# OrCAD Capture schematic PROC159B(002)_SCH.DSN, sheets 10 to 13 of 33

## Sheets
10 32. RESET SWITCHES: size C; title: RESET SWITCHES
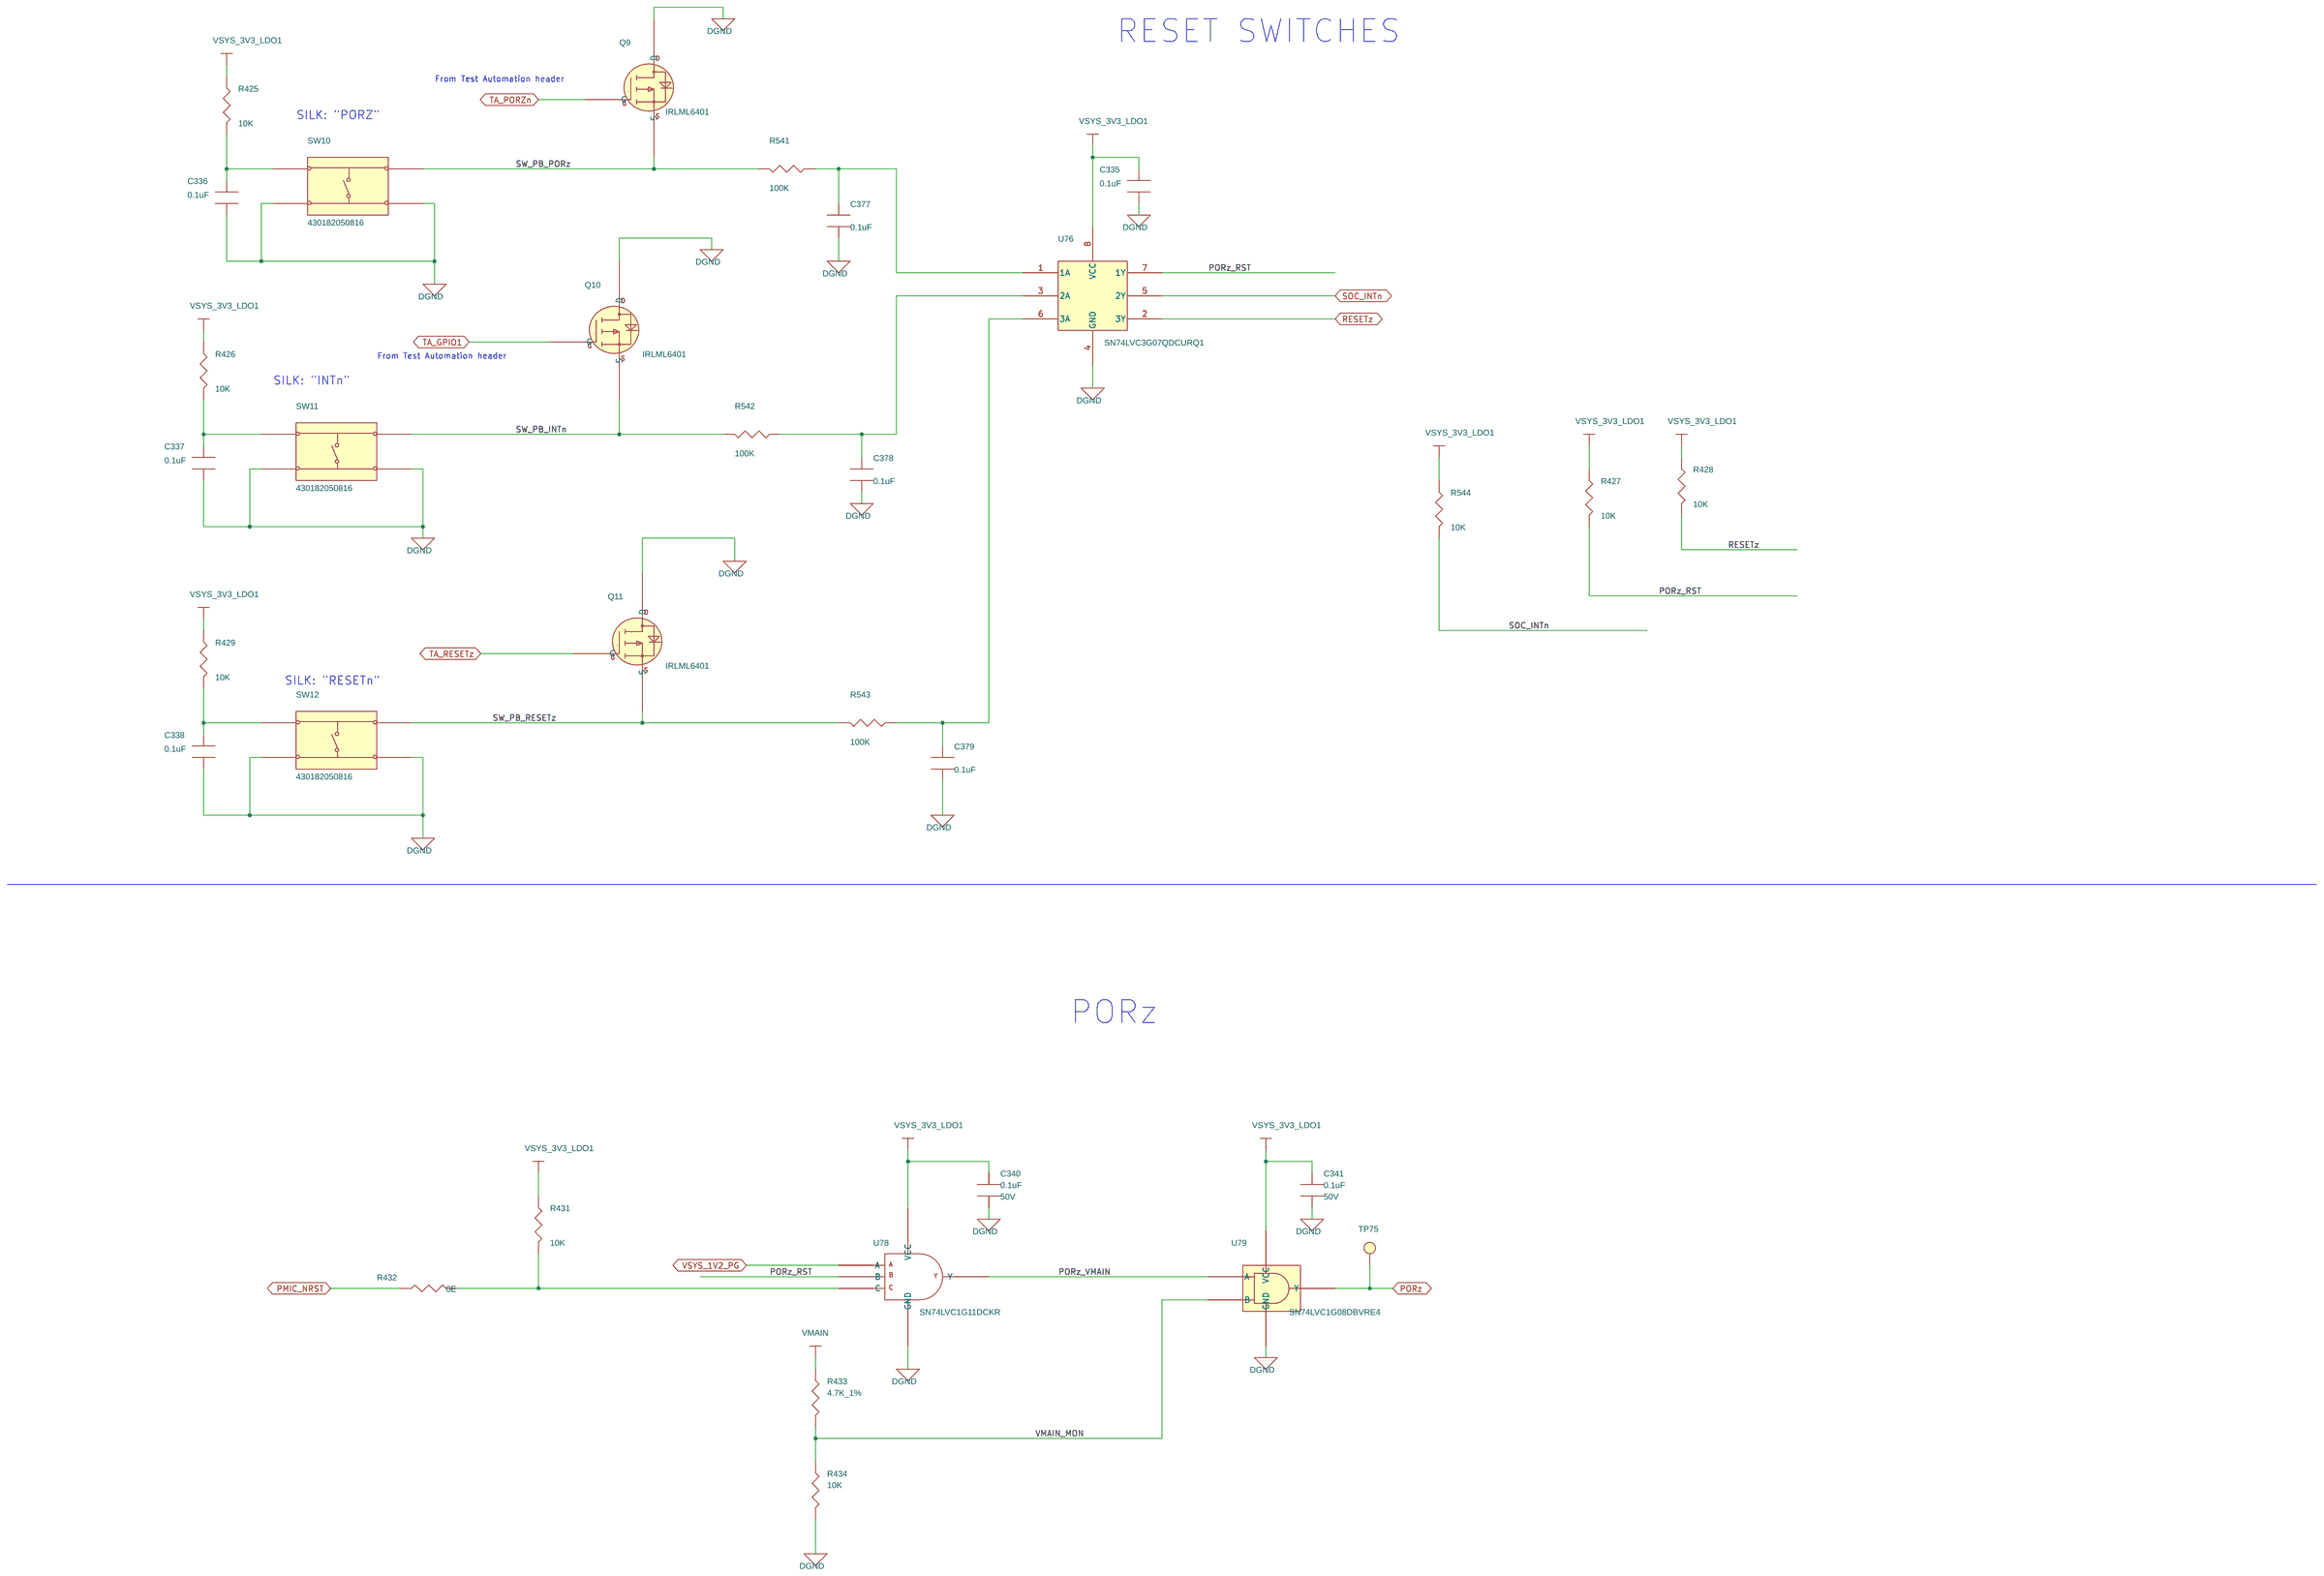
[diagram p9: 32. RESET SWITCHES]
11 25. BOOTMODE BUFFER AND SWITCH: size C; title: BOOTMODE BUFFER AND SWITCH
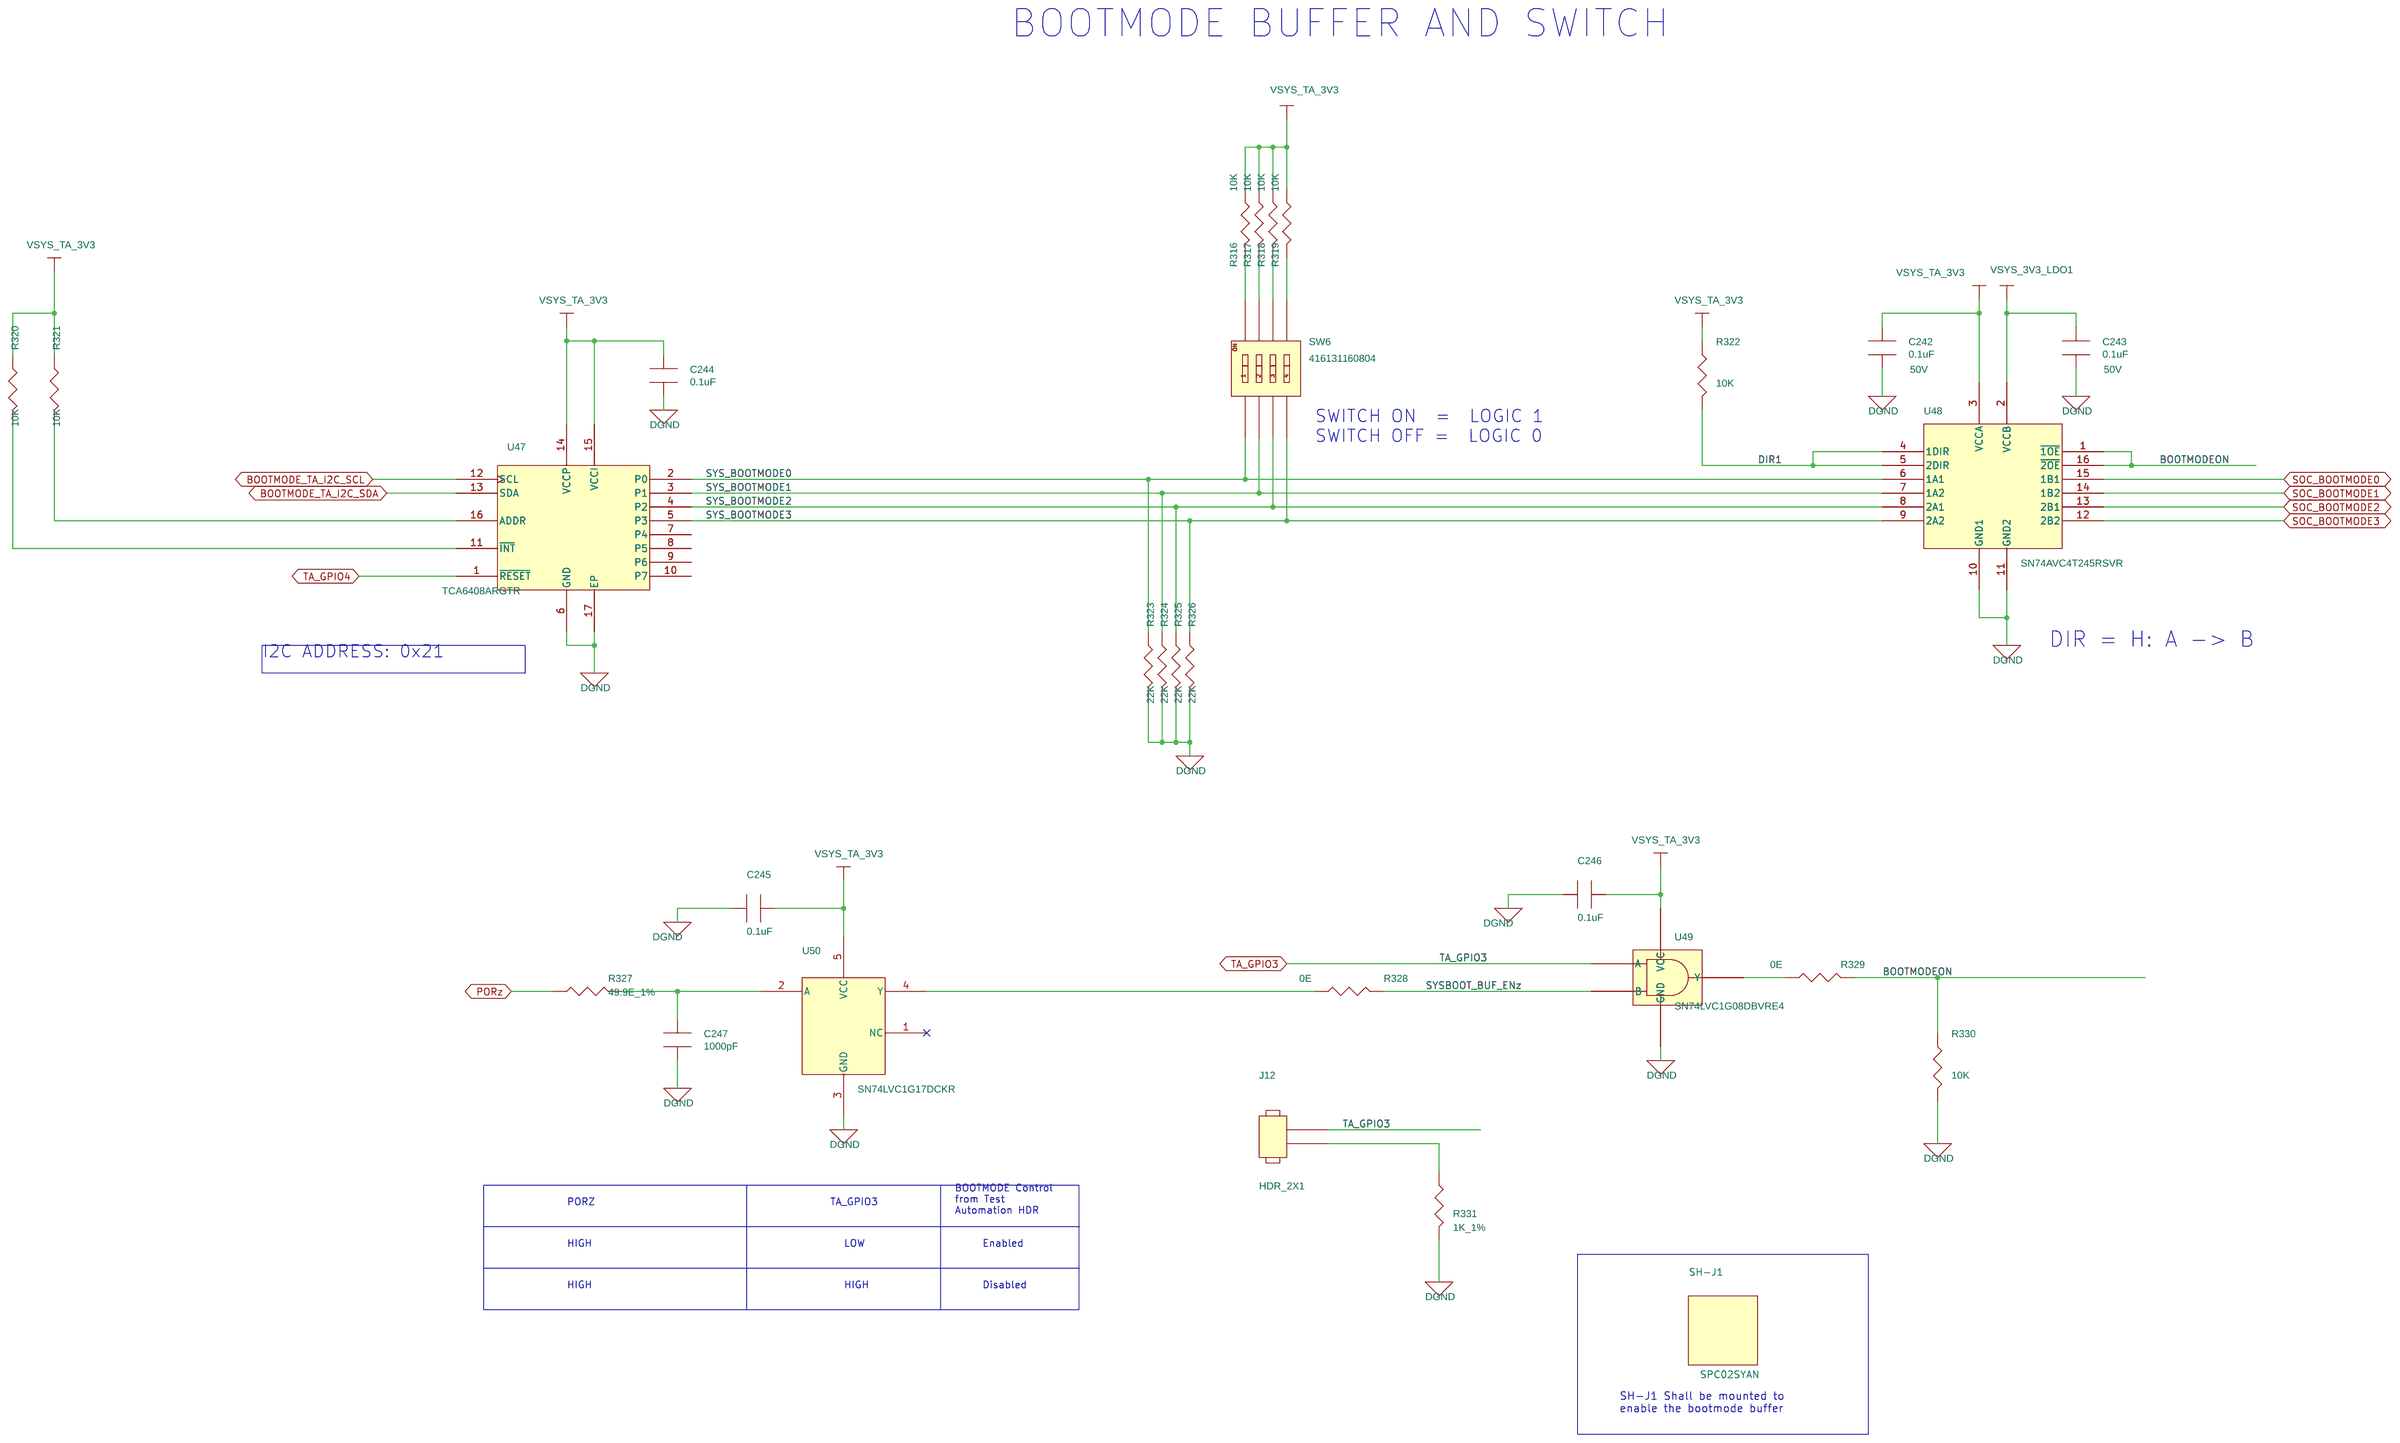
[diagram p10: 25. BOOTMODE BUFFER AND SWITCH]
12 28. LED DRIVER AND IO EXPANDER: size C; title: LED DRIVER AND IO EXPANDER
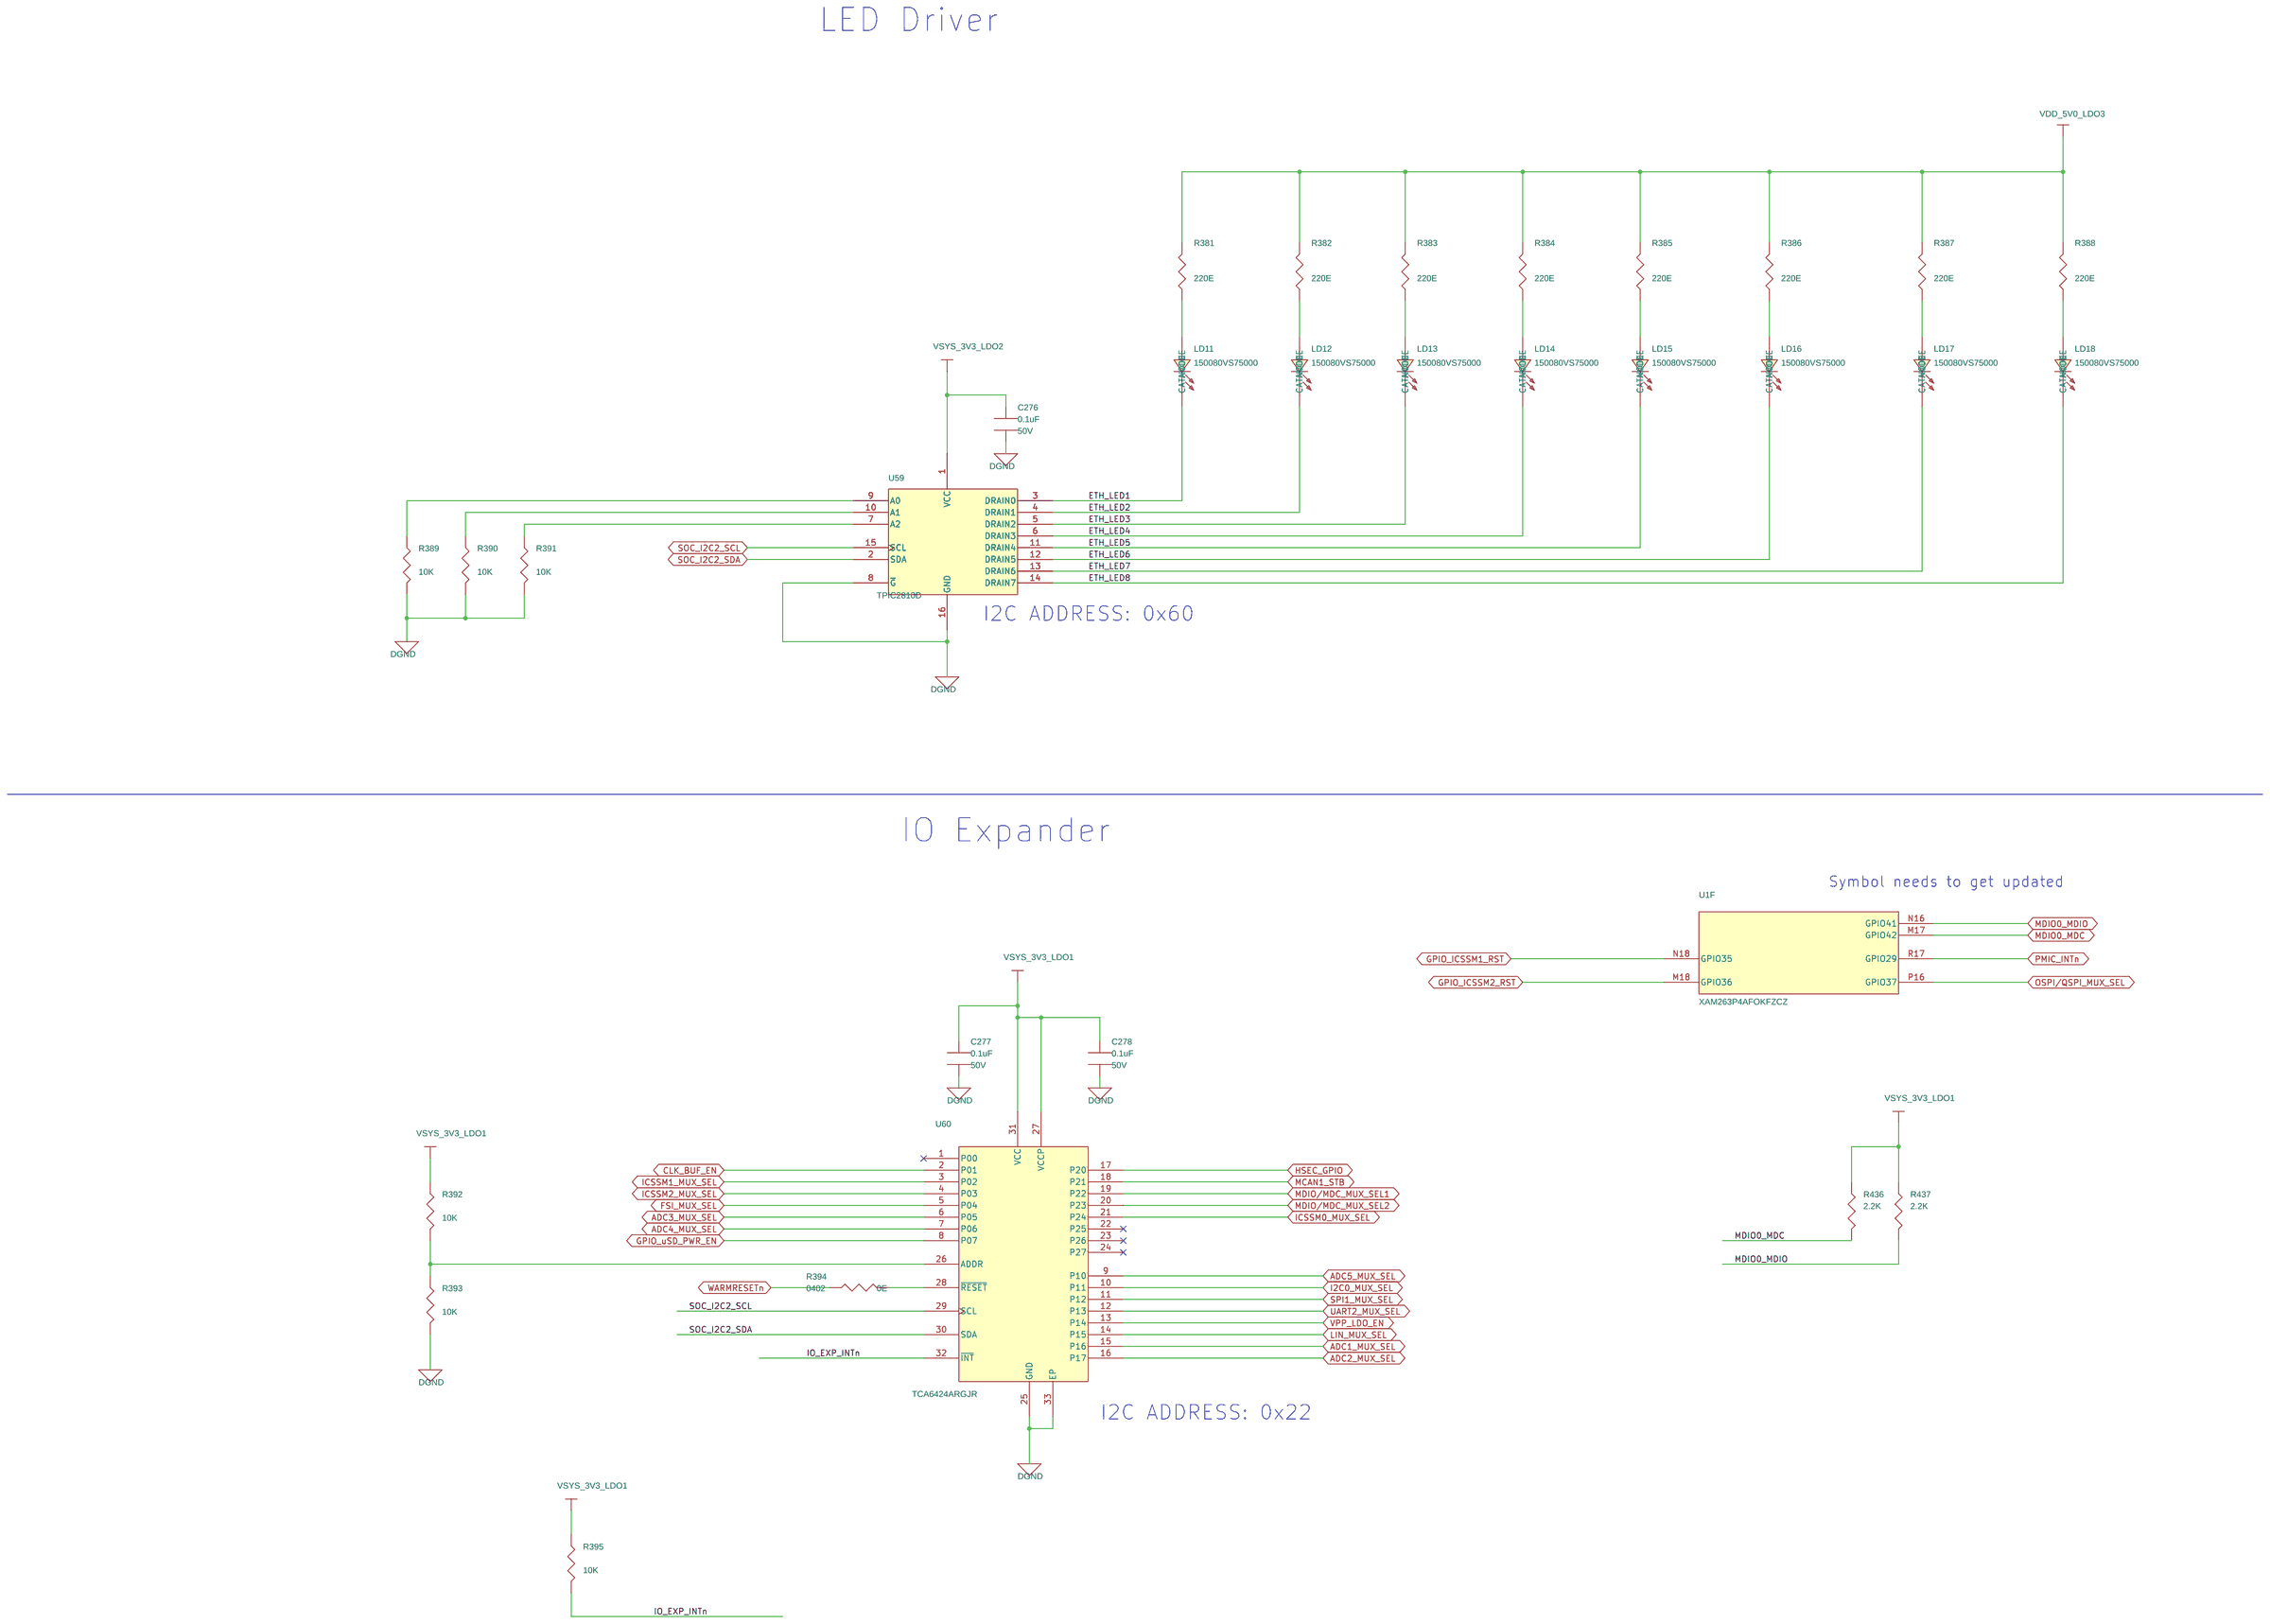
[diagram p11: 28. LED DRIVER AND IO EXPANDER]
13 18. MCAN AND FSI MUX: size C; title: MCAN AND FSI MUX
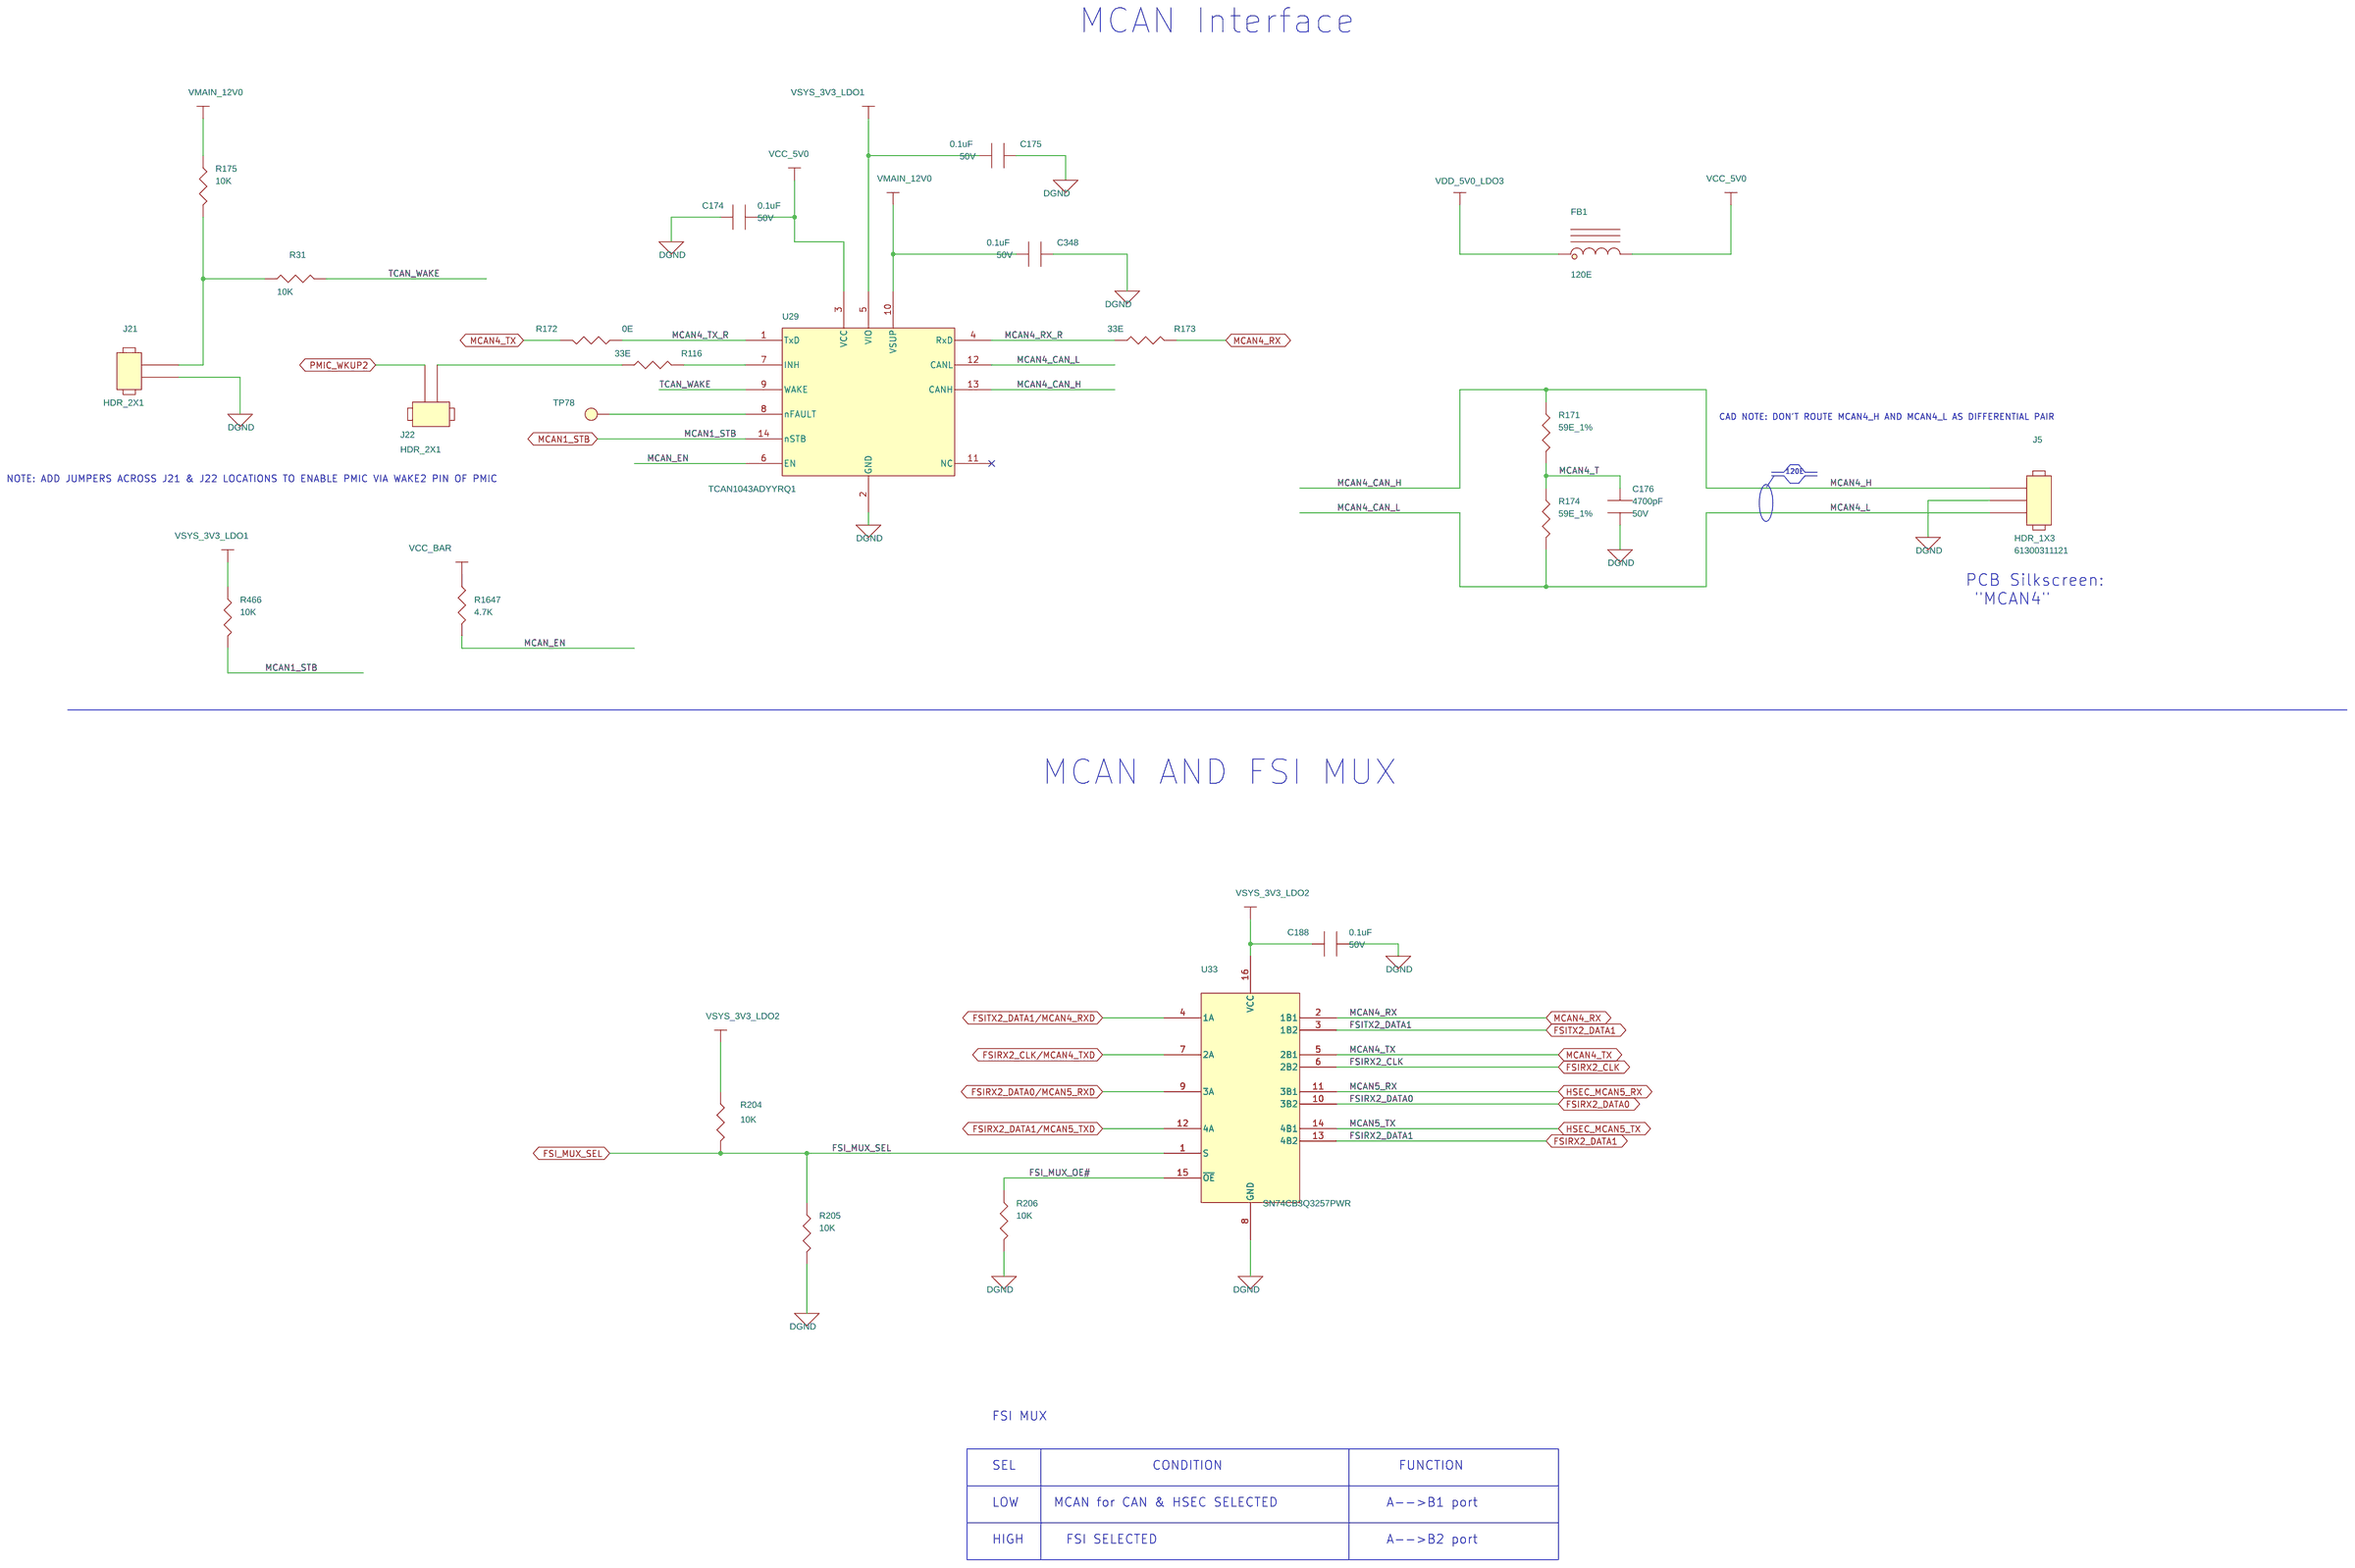
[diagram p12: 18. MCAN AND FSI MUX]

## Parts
sheet 18. MCAN AND FSI MUX
C174  0.1uF  [CAP0402_0-75]
C175  0.1uF  [CAP0402_0-75]
C176  4700pF  [CAP0402_0-75]
C188  0.1uF  [CAP0402_0-75]
C348  0.1uF  [CAP0402_0-75]
FB1  120E  [EMIFIL_BLM18S_0603_0-7]
J5  HDR_1X3  [HDR_1X3_100_S_T]
J21  HDR_2X1  [HDR_2X1_100_S_T_10-8]
J22  HDR_2X1  [HDR_2X1_100_S_T_10-8]
R31  10K  [RES0402_0-5]
R116  33E  [RES0402_0-5]
R171  59E_1%  [RES0402_0-5]
R172  0E  [RES0402_0-5]
R173  33E  [RES0402_0-5]
R174  59E_1%  [RES0402_0-5]
R175  10K  [RES0402_0-5]
R204  10K  [RES0402_0-5]
R205  10K  [RES0402_0-5]
R206  10K  [RES0402_0-5]
R466  10K  [RES0402_0-5]
R1647  4.7K  [RES0402_0-5]
TP78  TP20_SMD  [TP20_SMD]
U29  TCAN1043ADYYRQ1  [SOT23-14_1-1]
U33  SN74CB3Q3257PWR  [TSSOP16_25-59_205X180]
sheet 19. SOC-ICSS DP8386(Indust)
U1  XAM263P4AFOKFZCZ  [BGA324_31-49_590X590_1-4]  (sections A,B,C,D,E,F,G,H,I,J,K,L,M)
sheet 25. BOOTMODE BUFFER AND SWITCH
C242  0.1uF  [CAP0402_0-75]
C243  0.1uF  [CAP0402_0-75]
C244  0.1uF  [CAP0402_0-75]
C245  0.1uF  [CAP0402_0-75]
C246  0.1uF  [CAP0402_0-75]
C247  1000pF  [CAP0402_0-75]
J12  HDR_2X1  [HDR_2X1_100_S_T]
R316  10K  [RES0402_0-5]
R317  10K  [RES0402_0-5]
R318  10K  [RES0402_0-5]
R319  10K  [RES0402_0-5]
R320  10K  [RES0402_0-5]
R321  10K  [RES0402_0-5]
R322  10K  [RES0402_0-5]
R323  22K  [RES0402_0-5]
R324  22K  [RES0402_0-5]
R325  22K  [RES0402_0-5]
R326  22K  [RES0402_0-5]
R327  49.9E_1%  [RES0402_0-5]
R328  0E  [RES0402_0-5]
R329  0E  [RES0402_0-5]
R330  10K  [RES0402_0-5]
R331  1K_1%  [RES0402_0-5]
SH-J1  SPC02SYAN  [NA]
SW6  416131160804  [SW8_416131160804_260X230_SMD_2-7]
U47  TCA6408ARGTR  [QFN16_19-68_120X120_1_EP1-6]
U48  SN74AVC4T245RSVR  [UQFN16_TMUX1574_70X100_0-6]
U49  SN74LVC1G08DBVRE4  [SOT23-5]
U50  SN74LVC1G17DCKR  [SC70-5]
sheet 28. LED DRIVER AND IO EXPANDER
C276  0.1uF  [CAP0402_0-75]
C277  0.1uF  [CAP0402_0-75]
C278  0.1uF  [CAP0402_0-75]
LD11  150080VS75000  [LED_150080VS75000_80X50_SMD_0-8]
LD12  150080VS75000  [LED_150080VS75000_80X50_SMD_0-8]
LD13  150080VS75000  [LED_150080VS75000_80X50_SMD_0-8]
LD14  150080VS75000  [LED_150080VS75000_80X50_SMD_0-8]
LD15  150080VS75000  [LED_150080VS75000_80X50_SMD_0-8]
LD16  150080VS75000  [LED_150080VS75000_80X50_SMD_0-8]
LD17  150080VS75000  [LED_150080VS75000_80X50_SMD_0-8]
LD18  150080VS75000  [LED_150080VS75000_80X50_SMD_0-8]
R381  220E  [RES0402_0-5]
R382  220E  [RES0402_0-5]
R383  220E  [RES0402_0-5]
R384  220E  [RES0402_0-5]
R385  220E  [RES0402_0-5]
R386  220E  [RES0402_0-5]
R387  220E  [RES0402_0-5]
R388  220E  [RES0402_0-5]
R389  10K  [RES0402_0-5]
R390  10K  [RES0402_0-5]
R391  10K  [RES0402_0-5]
R392  10K  [RES0402_0-5]
R393  10K  [RES0402_0-5]
R394  0E  [RES0402_0-5]
R395  10K  [RES0402_0-5]
R436  2.2K  [RES0402_0-5]
R437  2.2K  [RES0402_0-5]
U59  TPIC2810D  [SOIC16_1-8]
U60  TCA6424ARGJR  [QFN32_19-68_200X200]
sheet 32. RESET SWITCHES
C335  0.1uF  [CAP0402_0-75]
C336  0.1uF  [CAP0402_0-75]
C337  0.1uF  [CAP0402_0-75]
C338  0.1uF  [CAP0402_0-75]
C340  0.1uF  [CAP0402_0-75]
C341  0.1uF  [CAP0402_0-75]
C377  0.1uF  [CAP0402_0-75]
C378  0.1uF  [CAP0402_0-75]
C379  0.1uF  [CAP0402_0-75]
Q9  IRLML6401  [TO_SOT23-123]
Q10  IRLML6401  [TO_SOT23-123]
Q11  IRLML6401  [TO_SOT23-123]
R425  10K  [RES0402_0-5]
R426  10K  [RES0402_0-5]
R427  10K  [RES0402_0-5]
R428  10K  [RES0402_0-5]
R429  10K  [RES0402_0-5]
R431  10K  [RES0402_0-5]
R432  0E  [RES0402_0-5]
R433  4.7K_1%  [RES0402_0-5]
R434  10K  [RES0402_0-5]
R541  100K  [RES0402_0-5]
R542  100K  [RES0402_0-5]
R543  100K  [RES0402_0-5]
R544  10K  [RES0402_0-5]
SW10  430182050816  [SW4_430182050816_240X240_SMD_5-2]
SW11  430182050816  [SW4_430182050816_240X240_SMD_5-2]
SW12  430182050816  [SW4_430182050816_240X240_SMD_5-2]
TP75  TP40_SMD  [TP40_SMD]
U76  SN74LVC3G07QDCURQ1  [VSSOP8_19-68_85X95]
U78  SN74LVC1G11DCKR  [SC70-6]
U79  SN74LVC1G08DBVRE4  [SOT23-5]

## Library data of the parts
C174 C175 C348 = CAP: CAP CERAMIC 0.1uF 50V 10% X7R 0402; Automotive Alternate_mfr_name: TDK; Automotive Alternate_mfr_part_number: CGA2B1X7R1C104K050BC; Chkd/date: MANIRAJA/261020; Crtd /date: ALVY/211020; Custom_Duty: 15%; Customs_HS_Code: 85322990; Direct Alternate_mfr_name: MURATA; Direct Alternate_mfr_part_number: GCM155R71C104JA55D; Distributor_name: DIGIKEY; Distributor_part_number: 490-10700-1-ND; Footprint Path: Y:\MIS_DATABASE\Library\ALTIUM_TOOL\PCB_FOOTPRINTS\Altium_Footprint_Lib.PcbLib; Height: 0.55MM; Library Path: Y:\MIS_DATABASE\Library\ALTIUM_TOOL\SCHEMATICS_PARTS\MS_DISCRETE_Library.schlib; Mfr_name: MURATA; Mfr_part_number: GRM155R71H104KE14D; Mistral Part No: 120011100014-R; Package: 0402; Part_type: CAPACITORS\CERAMIC; Project: J7_CP; RoHS: RoHS; Temperature: -55°C+125°C; Tolerance: 10%; Voltage: 50V; Wattage: NA; Weight: 3.1mg; Datasheet: Y:\MIS_DATABASE\DATASHEETS\CAPACITORS\GRM155R71H104KE14.PDF
C176 = CAP: CAP CERAMIC 4700pF 50V 10% X7R 0402; Automotive Alternate_mfr_name: TDK; Automotive Alternate_mfr_part_number: CGA2B2X7R1H472K050BA; Chkd/date: MANIRAJA/040419; Crtd /date: MANIRAJA/040419; Custom_Duty: 15%; Customs_HS_Code: 85322990; Direct Alternate_mfr_name: SAMSUNG; Direct Alternate_mfr_part_number: CL05B472KB5NNNC; Distributor_name: DIGIKEY; Distributor_part_number: 490-1308-1-ND; Footprint Path: Y:\MIS_DATABASE\Library\ALTIUM_TOOL\PCB_FOOTPRINTS\Altium_Footprint_Lib.PcbLib; Height: 0.55MM; Library Path: Y:\MIS_DATABASE\Library\ALTIUM_TOOL\SCHEMATICS_PARTS\MS_DISCRETE_Library.schlib; Mfr_name: MURATA; Mfr_part_number: GRM155R71H472KA01D; Mistral Part No: 120009030440-R; Package: 0402; Part_type: CAPACITORS\CERAMIC; Project: RED EYE; RoHS: RoHS; Temperature: -55°C+125°C; Tolerance: 10%; Voltage: 50V; Wattage: NA; Weight: 0.65mg; Datasheet: Y:\MIS_DATABASE\DATASHEETS\CAPACITORS\GRM155R71H472KA01.PDF
C188 C277 C278 C335-C338 C340 = CAP: CAP CERAMIC 0.1uF 50V 10% X7R 0402; Automotive Alternate_mfr_name: TDK; Automotive Alternate_mfr_part_number: CGA2B3X7R1H104K050BB; Chkd/date: MANIRAJA/261020; Crtd /date: ALVY/211020; Custom_Duty: 15%; Customs_HS_Code: 85322990; Direct Alternate_mfr_name: TDK; Direct Alternate_mfr_part_number: C1005X7R1H104K050BE; Distributor_name: DIGIKEY; Distributor_part_number: 490-10700-1-ND; Footprint Path: Y:\MIS_DATABASE\Library\ALTIUM_TOOL\PCB_FOOTPRINTS\Altium_Footprint_Lib.PcbLib; Height: 0.55MM; Library Path: Y:\MIS_DATABASE\Library\ALTIUM_TOOL\SCHEMATICS_PARTS\MS_DISCRETE_Library.schlib; Mfr_name: MURATA; Mfr_part_number: GRM155R71H104KE14D; Mistral Part No: 120011100014-R; Package: 0402; Part_type: CAPACITORS\CERAMIC; Project: J7_CP; RoHS: RoHS; Temperature: -55°C+125°C; Tolerance: 10%; Voltage: 50V; Wattage: NA; Weight: 3.1mg; Datasheet: Y:\MIS_DATABASE\DATASHEETS\CAPACITORS\GRM155R71H104KE14.PDF
FB1 = INDUCTOR_FERRITE: PASSIVE FILTER CHIP 120E 3A 0603; Chkd/date: MANIRAJA/241017; Crtd /date: BAVISH/080811; Custom_Duty: 24%; Customs_HS_Code: 85437099; Distributor_name: DIGIKEY; Distributor_part_number: 490-3996-1-ND; Height: 0.65MM; Mfr_name: MURATA; Mfr_part_number: BLM18SG121TN1D; Mistral Part No: 130011080020-R; Package: 0603; Part_type: FILTER; Project: ACRO_DM3730; RoHS: RoHS; Temperature: -55°C+125°C; Tolerance: NA; Voltage: NA; Wattage: NA; Weight: NA; Datasheet: Y:\MIS_DATABASE\DATASHEETS\DISCRETES\INDUCTORS\BLM18S.PDF
J5 = HEADER_3X1: CON HDR 1X3 2.54MM PITCH ST TH; Chkd/date: VASANTHA/211015; Crtd /date: VASANTHA/211015; Custom_Duty: 24%; Customs_HS_Code: 85369090; Distributor_name: DIGIKEY; Distributor_part_number: 732-5316-ND; Height: 8.54MM; Mfr_name: WURTH ELECTRONICS INC; Mfr_part_number: 61300311121; Mistral Part No: 150015100037-R; Package: THRU-HOLE; Part_type: CONNECTOR\HEADERS; Project: CYPHY_ROADKILL; RoHS: RoHS; Temperature: NA; Tolerance: NA; Voltage: NA; Wattage: NA; Weight: NA; Datasheet: Y:\MIS_DATABASE\DATASHEETS\CONNECTORS\6130XXX.PDF
J21 J22 = HEADER_2X1: CON HDR 2X1 2.54MM PITCH ST TH; Chkd/date: VASANTHA/060117; Crtd /date: MAZHAR/280405; Custom_Duty: 24%; Customs_HS_Code: 85369090; Distributor_name: DIGIKEY; Distributor_part_number: WM4000-ND; Footprint Path: Y:\MIS_DATABASE\Library\ALTIUM_TOOL\PCB_FOOTPRINTS\Altium_Footprint_Lib.PcbLib; Height: 10.79MM; Library Path: Y:\MIS_DATABASE\Library\ALTIUM_TOOL\SCHEMATICS_PARTS\MS_CONNECTOR_Library.schlib; Mfr_name: MOLEX; Mfr_part_number: 22-03-2021; Mistral Part No: 150009030246-R; Package: THRU-HOLE; Part_type: CONNECTOR\HEADERS; Project: FPGA EXTENDER CARD; RoHS: RoHS; Temperature: -0°C+75°C; Tolerance: NA; Voltage: NA; Wattage: NA; Weight: 139gm; Datasheet: Y:\MIS_DATABASE\DATASHEETS\CONNECTORS\HEADER_X4030.PDF
R31 R175 R205 R206 R466 = RESISTOR: RES 10K 1/16W 5% 0402; Assembly_Instruction: DNI; Chkd/date: VASANTHA/061216; Crtd /date: MAZHAR/230805; Custom_Duty: 15%; Customs_HS_Code: 85332119; Distributor_name: DIGIKEY; Distributor_part_number: 311-10KJRCT-ND; Footprint Path: Y:\MIS_DATABASE\Library\ALTIUM_TOOL\PCB_FOOTPRINTS\Altium_Footprint_Lib.PcbLib; Height: 0.40MM; Library Path: Y:\MIS_DATABASE\Library\ALTIUM_TOOL\SCHEMATICS_PARTS\MS_DISCRETE_Library.schlib; Mfr_name: YAGEO AMERICA; Mfr_part_number: RC0402JR-0710KL; Mistral Part No: 110011060021-R; Package: 0402; Part_type: RESISTORS\FIXED; Project: HSE; RoHS: RoHS; Temperature: -55°C+155°C; Tolerance: 5%; Voltage: NA; Wattage: 1/16W; Weight: 0.65mg; Datasheet: Y:\MIS_DATABASE\DATASHEETS\RESISTORS\RCXXXXL-SER_MAR18.PDF
R116 R173 = RESISTOR: RES 33E 1/10W 5% 0402; Chkd/date: VASANTHA/201216; Crtd /date: GEETHA/190406; Custom_Duty: 15%; Customs_HS_Code: 85332119; Distributor_name: DIGIKEY; Distributor_part_number: P33JCT-ND; Footprint Path: Y:\MIS_DATABASE\Library\ALTIUM_TOOL\PCB_FOOTPRINTS\Altium_Footprint_Lib.PcbLib; Height: 0.40MM; Library Path: Y:\MIS_DATABASE\Library\ALTIUM_TOOL\SCHEMATICS_PARTS\MS_DISCRETE_Library.schlib; Mfr_name: PANASONIC-ECG; Mfr_part_number: ERJ-2GEJ330X; Mistral Part No: 110009030699-R; Package: 0402; Part_type: RESISTORS\FIXED; Project: RED EYE; RoHS: RoHS; Temperature: -55°C+155°C; Tolerance: 5%; Voltage: NA; Wattage: 1/10W; Weight: 0.8mg; Datasheet: Y:\MIS_DATABASE\DATASHEETS\RESISTORS\PAN-ERJSER_NOV17.PDF
R171 R174 = RESISTOR: RES 59E 1/10W 1% 0402; Chkd/date: MAZHAR/151208; Crtd /date: USMAN/031208; Custom_Duty: 15%; Customs_HS_Code: 85332119; Distributor_name: DIGIKEY; Distributor_part_number: P59.0LCT-ND; Footprint Path: Y:\MIS_DATABASE\Library\ALTIUM_TOOL\PCB_FOOTPRINTS\Altium_Footprint_Lib.PcbLib; Height: 0.40MM; Library Path: Y:\MIS_DATABASE\Library\ALTIUM_TOOL\SCHEMATICS_PARTS\MS_DISCRETE_Library.schlib; Mfr_name: PANASONIC-ECG; Mfr_part_number: ERJ-2RKF59R0X; Mistral Part No: 110009031010-R; Package: 0402; Part_type: RESISTORS\FIXED; Project: KHAN_HSST; RoHS: RoHS; Temperature: -55°C+155°C; Tolerance: 1%; Voltage: NA; Wattage: 1/10W; Weight: 0.8mg; Datasheet: Y:\MIS_DATABASE\DATASHEETS\RESISTORS\PAN-ERJSER_NOV17.PDF
R172 R328 R329 R394 R432 = RESISTOR: RES 0E 1/10W JUMPER 0402; Chkd/date: VASANTHA/061216; Crtd /date: NAVEED/201014; Custom_Duty: 15%; Customs_HS_Code: 85332119; Distributor_name: DIGIKEY; Distributor_part_number: P0.0JCT-ND; Footprint Path: Y:\MIS_DATABASE\Library\ALTIUM_TOOL\PCB_FOOTPRINTS\Altium_Footprint_Lib.PcbLib; Height: 0.40MM; IBISSP_MODLES: VALUE REPEATING 2 TIME; Library Path: Y:\MIS_DATABASE\Library\ALTIUM_TOOL\SCHEMATICS_PARTS\MS_DISCRETE_Library.schlib; Mfr_name: PANASONIC-ECG; Mfr_part_number: ERJ-2GE0R00X; Mistral Part No: 110018030052-R; Package: 0402; Part_type: RESISTORS\FIXED; Project: AEGIS POM; RoHS: RoHS; Temperature: -55°C+155°C; Tolerance: NA; Voltage: NA; Wattage: 1/10W; Weight: 0.8mg; Datasheet: Y:\MIS_DATABASE\DATASHEETS\RESISTORS\PAN-ERJSER_NOV17.PDF
R204 R316-R322 R330 R389-R393 R395 R425-R429 R431 R434 R544 = RESISTOR: RES 10K 1/16W 5% 0402; Chkd/date: VASANTHA/061216; Crtd /date: MAZHAR/230805; Custom_Duty: 15%; Customs_HS_Code: 85332119; Distributor_name: DIGIKEY; Distributor_part_number: 311-10KJRCT-ND; Footprint Path: Y:\MIS_DATABASE\Library\ALTIUM_TOOL\PCB_FOOTPRINTS\Altium_Footprint_Lib.PcbLib; Height: 0.40MM; Library Path: Y:\MIS_DATABASE\Library\ALTIUM_TOOL\SCHEMATICS_PARTS\MS_DISCRETE_Library.schlib; Mfr_name: YAGEO AMERICA; Mfr_part_number: RC0402JR-0710KL; Mistral Part No: 110011060021-R; Package: 0402; Part_type: RESISTORS\FIXED; Project: HSE; RoHS: RoHS; Temperature: -55°C+155°C; Tolerance: 5%; Voltage: NA; Wattage: 1/16W; Weight: 0.65mg; Datasheet: Y:\MIS_DATABASE\DATASHEETS\RESISTORS\RCXXXXL-SER_MAR18.PDF
R1647 = RESISTOR: RES 4.7K 1/16W 5% 0402; Chkd/date: VASANTHA/281216; Crtd /date: BAVISH/010611; Custom_Duty: 15%; Customs_HS_Code: 85332119; Distributor_name: DIGIKEY; Distributor_part_number: 541-4.7KJCT-ND; Footprint Path: Y:\MIS_DATABASE\Library\ALTIUM_TOOL\PCB_FOOTPRINTS\Altium_Footprint_Lib.PcbLib; Height: 0.40MM; Library Path: Y:\MIS_DATABASE\Library\ALTIUM_TOOL\SCHEMATICS_PARTS\MS_DISCRETE_Library.schlib; Mfr_name: VISHAY; Mfr_part_number: CRCW04024K70JNED; Mistral Part No: 110011060001-R; Package: 0402; Part_type: RESISTORS\FIXED; Project: AM4515_EVM_LCD; RoHS: RoHS; Temperature: -55°C+155°C; Tolerance: 5%; Voltage: NA; Wattage: 1/16W; Weight: 0.65mg; Datasheet: Y:\MIS_DATABASE\DATASHEETS\RESISTORS\CRCW0603.PDF
TP78 = TESTPOINT: TESTPOINT CIR 20 SMD; Chkd/date: SHREESHAIL/171006; Crtd /date: MAZHAR/171006; Custom_Duty: NA; Customs_HS_Code: NA; Distributor_name: NA; Distributor_part_number: NA; Footprint Path: Y:\MIS_DATABASE\Library\ALTIUM_TOOL\PCB_FOOTPRINTS\Altium_Footprint_Lib.PcbLib; Height: NA; Library Path: Y:\MIS_DATABASE\Library\ALTIUM_TOOL\SCHEMATICS_PARTS\MS_DISCRETE_Library.schlib; MECHANICAL 3D STEP FILE: NA; Mfr_name: LOCAL; Mistral Part No: NA; Package: SMD; Project: BT MODULE_CSRBC04; RoHS: NA; Temperature: NA; Tolerance: NA; Voltage: NA; Wattage: NA; Weight: NA; Datasheet: NA
U29 = TCAN1043DQ1_SOIC14: IC AUTOMOTIVE LOW-POWER FAULT PROTECTED CAN FD TRANSCEIVER WITH SLEEP MODE TSOT23-14; Chkd/date: ALVY/140422; Crtd /date: ALVY/140422; Custom_Duty: 15%; Customs_HS_Code: 85423100; Distributor_name: NA; Distributor_part_number: NA; Footprint Path: Y:\MIS_DATABASE\Library\ALTIUM_TOOL\PCB_FOOTPRINTS\Altium_Footprint_Lib.PcbLib; Height: 1.10MM; Library Path: Y:\MIS_DATABASE\Library\ALTIUM_TOOL\SCHEMATICS_PARTS\MS_TELECOM_Library.schlib; Mfr_name: TEXAS INSTRUMENTS; Mistral Part No: 143022040001-R; Package: TSOT23-14; Part_type: ICS\TELECOM\TRANSCEIVER; Project: TI_AM62A SVB_BRD; RoHS: NA; Temperature: -40°C+150°C; Tolerance: NA; Voltage: NA; Wattage: NA; Weight: NA; Datasheet: Y:\MIS_DATABASE\DATASHEETS\ICS\TELECOM\TCAN1043-Q1.PDF
U33 = SN74CB3Q3257PWR_TSSOP16: IC 4BIT 1-OF-2 FET MULTIPLEXER/DEMULTIPLEXER TSSOP16; Chkd/date: SUHAS/251010; Crtd /date: USMAN/060109; Custom_Duty: 15%; Customs_HS_Code: 85423100; Distributor_name: DIGIKEY; Distributor_part_number: 296-19138-1-ND; Height: 1.20MM; Mfr_name: TEXAS INSTRUMENTS; Mistral Part No: 141009030117-R; Package: TSSOP16; Part_type: ICS\DIGITAL\COMBINATIONAL; Project: OMAP_EVM; RoHS: Sb/ Br FREE; Temperature: -40°C+85°C; Datasheet: Y:\MIS_DATABASE\DATASHEETS\ICS\DIGITAL\COMBINATIONAL\SN74CB3Q3257.PDF
U1 = XAM263P4ASOKFZCZ_BGA324: IC SIP AM263P SoC BGA324; Chkd/date: PRADEEP/030124; Crtd /date: PRADEEP/030124; Custom_Duty: 15%; Customs_HS_Code: 85423100; Distributor_name: NA; Distributor_part_number: NA; Footprint Path: Y:\MIS_DATABASE\Library\ALTIUM_TOOL\PCB_FOOTPRINTS\Altium_Footprint_Lib.PcbLib; Height: 1.40MM; MECHANICAL 3D STEP FILE: NA; Mfr_name: TEXAS INSTRUMENTS; Mistral Part No: 141324010001; Package: BGA324; Part_type: ICS\DIGITAL\FPGA; Project: AM263P_CC; RoHS: RoHS; Temperature: NA; Tolerance: NA; Voltage: NA; Wattage: NA; Weight: NA; Datasheet: Y:\MIS_DATABASE\DATASHEETS\ICS\INTERFACE\ZCZ0324A.PDF
C242-C246 C276 C341 = CAP: CAP CERAMIC 0.1uF 50V 10% X7R 0402; Chkd/date: MANIRAJA/261020; Crtd /date: ALVY/211020; Custom_Duty: 15%; Customs_HS_Code: 85322990; Distributor_name: DIGIKEY; Distributor_part_number: 490-10700-1-ND; Footprint Path: Y:\MIS_DATABASE\Library\ALTIUM_TOOL\PCB_FOOTPRINTS\Altium_Footprint_Lib.PcbLib; Height: 0.55MM; Library Path: Y:\MIS_DATABASE\Library\ALTIUM_TOOL\SCHEMATICS_PARTS\MS_DISCRETE_Library.schlib; Mfr_name: MURATA; Mfr_part_number: GRM155R71H104KE14D; Mistral Part No: 120011100014-R; Package: 0402; Part_type: CAPACITORS\CERAMIC; Project: J7_CP; RoHS: RoHS; Temperature: -55°C+125°C; Tolerance: 10%; Voltage: 50V; Wattage: NA; Weight: 3.1mg; Datasheet: Y:\MIS_DATABASE\DATASHEETS\CAPACITORS\GRM155R71H104KE14.PDF
C247 = CAP: CAP CERAMIC 1000pF 50V 5% C0G(NP0) 0402; Chkd/date: VASANTHA/281216; Crtd /date: MAZHAR/290806; Custom_Duty: 15%; Customs_HS_Code: 85322990; Distributor_name: DIGIKEY; Distributor_part_number: 490-3244-1-ND; Footprint Path: Y:\MIS_DATABASE\Library\ALTIUM_TOOL\PCB_FOOTPRINTS\Altium_Footprint_Lib.PcbLib; Height: 0.55MM; Library Path: Y:\MIS_DATABASE\Library\ALTIUM_TOOL\SCHEMATICS_PARTS\MS_DISCRETE_Library.schlib; Mfr_name: MURATA; Mfr_part_number: GRM1555C1H102JA01D; Mistral Part No: 120016110009-R; Package: 0402; Part_type: CAPACITORS\CERAMIC; Project: SVDO_RMB_MMA; RoHS: RoHS; Temperature: -55°C+125°C; Tolerance: 5%; Voltage: 50V; Wattage: NA; Weight: 6mg; Datasheet: Y:\MIS_DATABASE\DATASHEETS\CAPACITORS\MURATA-GXX-SER_NOV17.PDF
J12 = HEADER_2X1: CON HDR 2X1 2.54MM PITCH ST TH; Chkd/date: NAVEED/210714; Crtd /date: USMAN/031012; Custom_Duty: 24%; Customs_HS_Code: 85369090; Distributor_name: DIGIKEY; Distributor_part_number: WM8072-ND; Height: 5.60MM; Mfr_name: MOLEX; Mfr_part_number: 90120-0122; Mistral Part No: 150012100005-R; Package: THRU-HOLE; Part_type: CONNECTOR\HEADERS; Project: NPOL_FEP; RoHS: RoHS; Temperature: -55°C+125°C; Tolerance: NA; Voltage: NA; Wattage: NA; Weight: NA; Datasheet: Y:\MIS_DATABASE\DATASHEETS\CONNECTORS\90120-SERIES.PDF
R323-R326 = RESISTOR: RES 22K 1/16W 5% 0402; Chkd/date: MANIRAJA/310718; Crtd /date: BAVISH/021210; Custom_Duty: 15%; Customs_HS_Code: 85332119; Distributor_name: DIGIKEY; Distributor_part_number: 311-22KJRCT-ND; Footprint Path: Y:\MIS_DATABASE\Library\ALTIUM_TOOL\PCB_FOOTPRINTS\Altium_Footprint_Lib.PcbLib; Height: 0.40MM; Library Path: Y:\MIS_DATABASE\Library\ALTIUM_TOOL\SCHEMATICS_PARTS\MS_DISCRETE_Library.schlib; Mfr_name: YAGEO AMERICA; Mfr_part_number: RC0402JR-0722KL; Mistral Part No: 110010120021-R; Package: 0402; Part_type: RESISTORS\FIXED; Project: TE4; RoHS: RoHS; Temperature: -55°C+155°C; Tolerance: 5%; Voltage: NA; Wattage: 1/16W; Weight: 0.65mg; Datasheet: Y:\MIS_DATABASE\DATASHEETS\RESISTORS\RCXXXXL-SER_MAR18.PDF
R327 = RESISTOR: RES 49.9E 1/10W 1% 0402; Chkd/date: VASANTHA/201216; Crtd /date: MAZHAR/201005; Custom_Duty: 15%; Customs_HS_Code: 85332119; Distributor_name: DIGIKEY; Distributor_part_number: P49.9LCT-ND; Footprint Path: Y:\MIS_DATABASE\Library\ALTIUM_TOOL\PCB_FOOTPRINTS\Altium_Footprint_Lib.PcbLib; Height: 0.40MM; Library Path: Y:\MIS_DATABASE\Library\ALTIUM_TOOL\SCHEMATICS_PARTS\MS_DISCRETE_Library.schlib; Mfr_name: PANASONIC-ECG; Mfr_part_number: ERJ-2RKF49R9X; Mistral Part No: 110009030897-R; Package: 0402; Part_type: RESISTORS\FIXED; Project: RED EYE; RoHS: RoHS; Temperature: -55°C+155°C; Tolerance: 1%; Voltage: NA; Wattage: 1/10W; Weight: 0.8mg; Datasheet: Y:\MIS_DATABASE\DATASHEETS\RESISTORS\PAN-ERJSER_NOV17.PDF
R331 = RESISTOR: RES 1K 1/10W 1% 0402; Chkd/date: VASANTHA/281216; Crtd /date: MAZHAR/150506; Custom_Duty: 15%; Customs_HS_Code: 85332119; Distributor_name: DIGIKEY; Distributor_part_number: P1.00KLCT-ND; Footprint Path: Y:\MIS_DATABASE\Library\ALTIUM_TOOL\PCB_FOOTPRINTS\Altium_Footprint_Lib.PcbLib; Height: 0.40MM; Library Path: Y:\MIS_DATABASE\Library\ALTIUM_TOOL\SCHEMATICS_PARTS\MS_DISCRETE_Library.schlib; Mfr_name: PANASONIC-ECG; Mfr_part_number: ERJ-2RKF1001X; Mistral Part No: 110009030411-R; Package: 0402; Part_type: RESISTORS\FIXED; Project: VOCERA; RoHS: RoHS; Temperature: -55°C+155°C; Tolerance: 1%; Voltage: NA; Wattage: 1/10W; Weight: 0.8mg; Datasheet: Y:\MIS_DATABASE\DATASHEETS\RESISTORS\PAN-ERJSER_NOV17.PDF
SH-J1 = ACCESSORY: ACCESSORIE JUMPER SHORTING GOLD FLASH; Chkd/date: SUHAS\211010; Crtd /date: USMAN/301208; Distributor_name: DIGIKEY; Distributor_part_number: S9001-ND; Footprint Path: Y:\MIS_DATABASE\Library\ALTIUM_TOOL\PCB_FOOTPRINTS\Altium_Footprint_Lib.PcbLib; Library Path: Y:\MIS_DATABASE\Library\ALTIUM_TOOL\SCHEMATICS_PARTS\MS_MECHANICAL_Library.schlib; Mfr_name: SULLINS CONNECTOR; Mistral Part No: 160009030153-R; Part_type: ACCESSORIES; Project: SMART VIEW_NVR; RoHS: RoHS; Temperature: -55°C+105°C; Datasheet: Y:\MIS_DATABASE\DATASHEETS\MISC\MODULES\SPC02SYAN.PDF
SW6 = SW8_GDH04S04: SWITCH SLIDE SPST ST SMD; Chkd/date: MANIRAJA/120121; Crtd /date: MANIRAJA/120121; Custom_Duty: 24%; Customs_HS_Code: 85369090; Distributor_name: DIGIKEY; Distributor_part_number: 732-3854-1-ND; Footprint Path: Y:\MIS_DATABASE\Library\ALTIUM_TOOL\PCB_FOOTPRINTS\Altium_Footprint_Lib.PcbLib; Height: 2.65MM; Library Path: Y:\MIS_DATABASE\Library\ALTIUM_TOOL\SCHEMATICS_PARTS\MS_SWITCH_Library.schlib; Mfr_name: WURTH ELEKTRONIK; Mistral Part No: 130021010016-R; Package: SMD; Part_type: ELECTRO-MECHANICAL\SWITCH; Project: AM223X_LP; RoHS: RoHS; Temperature: -40°C+85°C; Tolerance: NA; Voltage: NA; Wattage: NA; Weight: 110mg; Datasheet: Y:\MIS_DATABASE\DATASHEETS\MISC\SWITCHES\4161311608XX.PDF
U47 = TCA6408ARGTR_VQFN16: IC 8-BIT I2C AND SMBUS I/O EXPANDER WITH INTERRUPT O/P VQFN16; Chkd/date: MANIRAJA/151018; Crtd /date: MANIRAJA/151018; Custom_Duty: 15%; Customs_HS_Code: 85423100; Distributor_name: DIGIKEY; Distributor_part_number: 296-24825-1-ND; Footprint Path: Y:\MIS_DATABASE\Library\ALTIUM_TOOL\PCB_FOOTPRINTS\Altium_Footprint_Lib.PcbLib; Height: 1.00MM; Library Path: Y:\MIS_DATABASE\Library\ALTIUM_TOOL\SCHEMATICS_PARTS\MS_MISCINTERFACE_Library.schlib; Mfr_name: TEXAS INSTRUMENTS; Mistral Part No: 141018100011-R; Package: VQFN16; Part_type: ICS\INTERFACE; Project: TI_60GHz-AOP; RoHS: RoHS; Temperature: -40°C+85°C; Tolerance: NA; Voltage: NA; Wattage: NA; Weight: 24.1mg; Datasheet: Y:\MIS_DATABASE\DATASHEETS\ICS\INTERFACE\TCA6408AXX.PDF
U48 = SN74AVC4T245RSV_UQFN16: IC 2-BIT BUS TRANSCEIVER WITH CONFIGURABLE VOLTAGE TRANSLATION AND 3 STATE O/P UQFN16; Chkd/date: MANIRAJA/040520; Crtd /date: BAVISH/190411; Custom_Duty: 15%; Customs_HS_Code: 85423100; Distributor_name: DIGIKEY; Distributor_part_number: 296-24366-1-ND; Footprint Path: Y:\MIS_DATABASE\Library\ALTIUM_TOOL\PCB_FOOTPRINTS\Altium_Footprint_Lib.PcbLib; Height: 0.55MM; Library Path: Y:\MIS_DATABASE\Library\ALTIUM_TOOL\SCHEMATICS_PARTS\MS_BUSDRIVERTRANSCEIVER_Library.schlib; Mfr_name: TEXAS INSTRUMENTS; Mistral Part No: 141011040011-R; Package: UQFN16; Part_type: ICS\DIGITAL\BUSTRANSCEIVER; Project: HMC; RoHS: RoHS; Temperature: -40°C+85°C; Tolerance: NA; Voltage: NA; Wattage: NA; Weight: 41mg; Datasheet: Y:\MIS_DATABASE\DATASHEETS\ICS\DIGITAL\BUSTRANSCEIVER\SN74AVC4T245-SER.PDF
U49 U79 = SN74LVC1G08DBVRE4_SOT23-5: IC SINGLE 2-INPUT POSITIVE AND GATE SOT23-5; Automotive Alternate_mfr_name: TEXAS INSTRUMENTS; Automotive Alternate_mfr_part_number: SN74LVC1G08QDBVRQ1; Chkd/date: SUHAS/221010; Crtd /date: USMAN/151008; Custom_Duty: 15%; Customs_HS_Code: 85423100; Distributor_name: DIGIKEY; Distributor_part_number: SN74LVC1G08DBVRE4-ND; Height: 1.45MM; Mfr_name: TEXAS INSTRUMENTS; Mistral Part No: 141009060026-R; Part_type: ICS\DIGITAL\GATES; Project: KHAN_MAIN; RoHS: Sb/ Br FREE; Temperature: -40°C+85°C; Datasheet: Y:\MIS_DATABASE\DATASHEETS\ICS\DIGITAL\GATES\SN74LVC1G08.PDF
U50 = SN74LVC1G17DCKR_SC70-5: IC SINGLE SCHMITT-TRIGGER BUFFER SC70-5; Chkd/date: MAZHAR/011210; Crtd /date: BAVISH/251110; Custom_Duty: 15%; Customs_HS_Code: 85423100; Distributor_name: DIGIKEY; Distributor_part_number: 296-11934-1-ND; Height: 1.10MM; Mfr_name: TEXAS INSTRUMENTS; Mistral Part No: 141010110012-R; Part_type: ICS\DIGITAL\COMBINATIONAL; Project: ITS-PWR_CARD; RoHS: RoHS; Temperature: -40°C+85°C; Tolerance: NA; Voltage: NA; Wattage: NA; Weight: NA; Datasheet: Y:\MIS_DATABASE\DATASHEETS\ICS\DIGITAL\COMBINATIONAL\SN74LVC1G17DCK.PDF
LD11-LD18 = DIODE_LED: DIODE LED BRIGHT GREEN SMD; Chkd/date: MANIRAJA/180820; Crtd /date: ALVY/180820; Custom_Duty: 24%; Customs_HS_Code: 85439000; Distributor_name: DIGIKEY; Distributor_part_number: 732-4986-1-ND; Footprint Path: Y:\MIS_DATABASE\Library\ALTIUM_TOOL\PCB_FOOTPRINTS\Altium_Footprint_Lib.PcbLib; Height: 0.80MM; Library Path: Y:\MIS_DATABASE\Library\ALTIUM_TOOL\SCHEMATICS_PARTS\MS_OPTO_Library.schlib; Mfr_name: WURTH ELECTRONICS; Mistral Part No: 130020080012-R; Package: SMD; Part_type: OPTO\LED; Project: AM64x_EVM_BRD; RoHS: RoHS; Temperature: -40°C+85°C; Tolerance: NA; Voltage: NA; Wattage: NA; Weight: 10mg; Datasheet: Y:\MIS_DATABASE\DATASHEETS\DISCRETES\LEDS\150080VS75000.PDF
R381-R388 = RESISTOR: RES 220E 1/10W 5% 0402; Chkd/date: VASANTHA/291216; Crtd /date: GEETHA/260406; Custom_Duty: 15%; Customs_HS_Code: 85332119; Distributor_name: DIGIKEY; Distributor_part_number: P220JCT-ND; Footprint Path: Y:\MIS_DATABASE\Library\ALTIUM_TOOL\PCB_FOOTPRINTS\Altium_Footprint_Lib.PcbLib; Height: 0.40MM; Library Path: Y:\MIS_DATABASE\Library\ALTIUM_TOOL\SCHEMATICS_PARTS\MS_DISCRETE_Library.schlib; Mfr_name: PANASONIC-ECG; Mfr_part_number: ERJ-2GEJ221X; Mistral Part No: 110009030506-R; Package: 0402; Part_type: RESISTORS\FIXED; Project: RED EYE; RoHS: RoHS; Temperature: -55°C+155°C; Tolerance: 5%; Voltage: NA; Wattage: 1/10W; Weight: 0.8mg; Datasheet: Y:\MIS_DATABASE\DATASHEETS\RESISTORS\PAN-ERJSER_NOV17.PDF
R436 R437 = RESISTOR: RES 2.2K 1/10W 5% 0402; Chkd/date: SHREESHAIL/210406; Crtd /date: GEETHA/200406; Custom_Duty: 15%; Customs_HS_Code: 85332119; Distributor_name: DIGIKEY; Distributor_part_number: P2.2KJCT-ND; Footprint Path: Y:\MIS_DATABASE\Library\ALTIUM_TOOL\PCB_FOOTPRINTS\Altium_Footprint_Lib.PcbLib; Height: 0.40MM; Library Path: Y:\MIS_DATABASE\Library\ALTIUM_TOOL\SCHEMATICS_PARTS\MS_DISCRETE_Library.schlib; Mfr_name: PANASONIC-ECG; Mfr_part_number: ERJ-2GEJ222X; Mistral Part No: 110009030429-R; Package: 0402; Part_type: RESISTORS\FIXED; Project: RED EYE; RoHS: RoHS; Temperature: -55°C+155°C; Tolerance: 5%; Voltage: NA; Wattage: 1/10W; Weight: 0.8mg; Datasheet: Y:\MIS_DATABASE\DATASHEETS\RESISTORS\PAN-ERJSER_NOV17.PDF
U59 = TPIC2810D_SOIC16: IC 8-BIT LED DRIVER WITH I2C INTERFACE SOIC16; Chkd/date: MANIRAJA/230817; Crtd /date: MANIRAJA/220817; Custom_Duty: 15%; Customs_HS_Code: 85423100; Distributor_name: DIGIKEY; Distributor_part_number: 296-13746-5-ND; Height: 1.75MM; Mfr_name: TEXAS INSTRUMENTS; Mistral Part No: 141017080026-R; Package: SOIC16; Part_type: ICS\INTERFACE; Project: TI_MAXIE_CPB; RoHS: RoHS; Temperature: -40°C+125°C; Tolerance: NA; Voltage: NA; Wattage: NA; Weight: NA; Datasheet: Y:\MIS_DATABASE\DATASHEETS\ICS\INTERFACE\TPIC2810D.PDF
U60 = TCA6424ARGJR_QFN32: IC I2C I/O EXPANDER 24B UQFN32; Chkd/date: NAVEED/100715; Crtd /date: NAVEED/100914; Custom_Duty: 15%; Customs_HS_Code: 85423100; Distributor_name: DIGIKEY; Distributor_part_number: 296-27844-1-ND; Height: 0.60MM; Mfr_name: TEXAS INSTRUMENTS; Mistral Part No: 141014090009-R; Package: UQFN32; Part_type: ICS\DIGITAL\BUSTRANSCEIVER; Project: ZK_BIOMETRIC; RoHS: RoHS; Temperature: -40°C+85°C; Weight: NA; Datasheet: Y:\MIS_DATABASE\DATASHEETS\ICS\DIGITAL\BUSTRANSCEIVER\TCA6424AR.PDF
C377-C379 = CAP: CAP CERAMIC 0.1uF 50V 10% X7R 0402; Alt_Mfr_name: YAGEO AMERICA; Alt_Mfr_part_number: CC0402KRX5R8BB104; Chkd/date: MANIRAJA/261020; Crtd /date: ALVY/211020; Custom_Duty: 15%; Customs_HS_Code: 85322990; Distributor_name: DIGIKEY; Distributor_part_number: 490-10700-1-ND; Footprint Path: Y:\MIS_DATABASE\Library\ALTIUM_TOOL\PCB_FOOTPRINTS\Altium_Footprint_Lib.PcbLib; Height: 0.55MM; Library Path: Y:\MIS_DATABASE\Library\ALTIUM_TOOL\SCHEMATICS_PARTS\MS_DISCRETE_Library.schlib; Mfr_name: MURATA; Mfr_part_number: GRM155R71H104KE14D; Mistral Part No: 120011100014-R; Package: 0402; Part_type: CAPACITORS\CERAMIC; Project: J7_CP; RoHS: RoHS; Temperature: -55°C+125°C; Tolerance: 10%; Voltage: 50V; Wattage: NA; Weight: 3.1mg; Datasheet: Y:\MIS_DATABASE\DATASHEETS\CAPACITORS\GRM155R71H104KE14.PDF
Q9-Q11 = MOSFET_IRLML6401TR: TRANSISTOR MOSFET P-CHANNEL SOT23-3; Chkd/date: SHREESHAIL/020206; Crtd /date: MAZHAR/040505; Custom_Duty: 15%; Customs_HS_Code: 85412900; Distributor_name: DIGIKEY; Distributor_part_number: IRLML6401PBFCT-ND; Height: 1.11MM; Mfr_name: IRF; Mfr_part_number: IRLML6401TRPBF; Mistral Part No: 130009031213-P; Package: SOT23-3; Part_type: TRANSISTOR\MOSFET; Project: G4_SVGA; RoHS: Pb-Free; Temperature: -55°C+150°C; Tolerance: NA; Voltage: NA; Wattage: NA; Weight: NA; Datasheet: Y:\MIS_DATABASE\DATASHEETS\DISCRETES\TRANSISTORS_FETS\IRLML6401.PDF
R433 = RESISTOR: RES 4.7K 1/16W 1% 0402; Chkd/date: VASANTHA/061216; Crtd /date: USMAN/070109; Custom_Duty: 15%; Customs_HS_Code: 85332119; Distributor_name: DIGIKEY; Distributor_part_number: 541-4.70KLCT-ND; Footprint Path: Y:\MIS_DATABASE\Library\ALTIUM_TOOL\PCB_FOOTPRINTS\Altium_Footprint_Lib.PcbLib; Height: 0.40MM; Library Path: Y:\MIS_DATABASE\Library\ALTIUM_TOOL\SCHEMATICS_PARTS\MS_DISCRETE_Library.schlib; Mfr_name: VISHAY; Mfr_part_number: CRCW04024K70FKED; Mistral Part No: 110009030797-R; Package: 0402; Part_type: RESISTORS\FIXED; Project: OMAP_EVM; RoHS: RoHS; Temperature: -55°C+155°C; Tolerance: 1%; Voltage: NA; Wattage: 1/16W; Weight: 0.65mg; Datasheet: Y:\MIS_DATABASE\DATASHEETS\RESISTORS\CRCW0603.PDF
R541-R543 = RESISTOR: RES 100K 1/16W 5% 0402; Chkd/date: VASANTHA/061216; Crtd /date: BAVISH/010611; Custom_Duty: 15%; Customs_HS_Code: 85332119; Distributor_name: DIGIKEY; Distributor_part_number: 541-100KJCT-ND; Footprint Path: Y:\MIS_DATABASE\Library\ALTIUM_TOOL\PCB_FOOTPRINTS\Altium_Footprint_Lib.PcbLib; Height: 0.40MM; Library Path: Y:\MIS_DATABASE\Library\ALTIUM_TOOL\SCHEMATICS_PARTS\MS_DISCRETE_Library.schlib; Mfr_name: VISHAY; Mfr_part_number: CRCW0402100KJNED; Mistral Part No: 110011060002-R; Package: 0402; Part_type: RESISTORS\FIXED; Project: AM4515_EVM_LCD; RoHS: RoHS; Temperature: -55°C+155°C; Tolerance: 5%; Voltage: NA; Wattage: 1/16W; Weight: 0.65mg; Datasheet: Y:\MIS_DATABASE\DATASHEETS\RESISTORS\CRCW0603.PDF
SW10-SW12 = SW4_430182050816: SWITCH TACTILE SPST ST SMD; Chkd/date: MANIRAJA/180121; Crtd /date: ALVY/180121; Custom_Duty: 24%; Customs_HS_Code: 85369090; Distributor_name: DIGIKEY; Distributor_part_number: 732-7005-1-ND; Footprint Path: Y:\MIS_DATABASE\Library\ALTIUM_TOOL\PCB_FOOTPRINTS\Altium_Footprint_Lib.PcbLib; Height: 5.15MM; Library Path: Y:\MIS_DATABASE\Library\ALTIUM_TOOL\SCHEMATICS_PARTS\MS_SWITCH_Library.schlib; Mfr_name: WURTH ELEKTRONIK; Mistral Part No: 130021010021-R; Package: SMD; Part_type: ELECTRO-MECHANICAL\SWITCH; Project: TI_DRA829 SK EVM BRD; RoHS: RoHS; Temperature: -40°C+85°C; Tolerance: NA; Voltage: NA; Wattage: NA; Weight: 220mg; Datasheet: Y:\MIS_DATABASE\DATASHEETS\MISC\SWITCHES\4301X2XXX816.PDF
TP75 = TESTPOINT: TESTPOINT CIR 40 SMD; Chkd/date: MAZHAR/190505; Crtd /date: MAZHAR/190505; Distributor_name: NA; Distributor_part_number: NA; Footprint Path: Y:\MIS_DATABASE\Library\ALTIUM_TOOL\PCB_FOOTPRINTS\Altium_Footprint_Lib.PcbLib; Height: NA; Library Path: Y:\MIS_DATABASE\Library\ALTIUM_TOOL\SCHEMATICS_PARTS\MS_DISCRETE_Library.schlib; MECHANICAL 3D STEP FILE: NA; Mfr_name: LOCAL; Mistral Part No: 130009030933; Package: SMD; Project: RAINIER-3; RoHS: NA; Temperature: NA; Tolerance: NA; Voltage: NA; Wattage: NA; Weight: NA; Datasheet: NA
U76 = SN74LVC3G07QDCURQ1_VSSOP8: IC BUFFER/DRIVER TRIPLE OPEN-DRAIN OUTPUT VSSOP8; Chkd/date: USMAN/230412; Crtd /date: CHAITHANYA/200412; Custom_Duty: 15%; Customs_HS_Code: 85423100; Distributor_name: DIGIKEY; Distributor_part_number: 296-23710-1-ND; Height: 0.90MM; Mfr_name: TEXAS INSTRUMENTS; Mistral Part No: 141012040013-R; Package: VSSOP8; Part_type: ICS\DIGITAL\COMBINATIONAL; Project: GATEWAY; RoHS: RoHS; Temperature: -40°C+125°C; Tolerance: NA; Voltage: NA; Wattage: NA; Weight: NA; Datasheet: Y:\MIS_DATABASE\DATASHEETS\ICS\DIGITAL\COMBINATIONAL\SN74LVC3G07-Q1.PDF
U78 = SN74LVC1G11DCKR_SC70-6: IC SINGLE 3-INPUT POSITIVE-AND GATE SC70-6; Chkd/date: SHREESHAIL/220506; Crtd /date: MAZHAR/150506; Custom_Duty: 15%; Customs_HS_Code: 85423100; Distributor_name: DIGIKEY; Distributor_part_number: 296-18066-1-ND; Height: 1.10MM; Mfr_name: TEXAS INSTRUMENTS; Mistral Part No: 141009030230-R; Part_type: ICS\DIGITAL\GATES; Project: VOCERA; RoHS: Sb/ Br FREE; Datasheet: Y:\MIS_DATABASE\DATASHEETS\ICS\DIGITAL\GATES\SN74LVC1G.PDF

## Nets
DGND: C174.1 C175.1 C176.2 C188.2 C242.2 C243.2 C244.2 C245.1 C246.1 C247.2 C276.2 C277.2 C278.2 C335.2 C336.2 C337.2 C338.2 C340.2 C341.2 C348.1 C377.1 C378.1 C379.1 J5.2 J21.2 Q9.3(D) Q10.3(D) Q11.3(D) R205.2 R206.2 R323.1 R324.1 R325.1 R326.1 R330.1 R331.2 R389.1 R390.1 R391.1 R393.1 R434.2 SW10.1 SW10.3 SW11.1 SW11.3 SW12.1 SW12.3 U29.2(GND) U33.8(GND) U47.6(GND) U47.17(EP) U48.10(GND1) U48.11(GND2) U49.3(GND) U50.3(GND) U59.8(~{G}) U59.16(GND) U60.25(GND) U60.33(EP) U76.4(GND) U78.2(GND) U79.3(GND) ; also on sheet 1 2 3 4 6 7 8 9 14 15 16 17 24 25 26 27 28 29 30 32 33
VCC_5V0: C174.2 FB1.2 U29.3(VCC) ; also on sheet 6
VDD_5V0_LDO3: FB1.1 R381.2 R382.2 R383.2 R384.2 R385.2 R386.2 R387.2 R388.2 ; also on sheet 9 30
ADC1_MUX_SEL: U60.15(P16) ; also on sheet 6
ADC2_MUX_SEL: U60.16(P17) ; also on sheet 6
ADC3_MUX_SEL: U60.6(P05) ; also on sheet 2
ADC4_MUX_SEL: U60.7(P06) ; also on sheet 2
ADC5_MUX_SEL: U60.9(P10) ; also on sheet 2
BOOTMODE_TA_I2C_SCL: U47.12(SCL) ; also on sheet 3 28
BOOTMODE_TA_I2C_SDA: U47.13(SDA) ; also on sheet 3 28
BOOTMODEON: R329.1 R330.2 U48.1(~{1OE}) U48.16(~{2OE})
CLK_BUF_EN: U60.2(P01) ; also on sheet 9
DIR1: R322.1 U48.4(1DIR) U48.5(2DIR)
ETH_LED1: LD11.1(CATHODE) U59.3(DRAIN0)
ETH_LED2: LD12.1(CATHODE) U59.4(DRAIN1)
ETH_LED3: LD13.1(CATHODE) U59.5(DRAIN2)
ETH_LED4: LD14.1(CATHODE) U59.6(DRAIN3)
ETH_LED5: LD15.1(CATHODE) U59.11(DRAIN4)
ETH_LED6: LD16.1(CATHODE) U59.12(DRAIN5)
ETH_LED7: LD17.1(CATHODE) U59.13(DRAIN6)
ETH_LED8: LD18.1(CATHODE) U59.14(DRAIN7)
FSI_MUX_OE#: R206.1 U33.15(~{OE})
FSI_MUX_SEL: R204.2 R205.1 U33.1(S) U60.5(P04)
FSIRX2_CLK: U33.6(2B2) ; also on sheet 27
FSIRX2_CLK/MCAN4_TXD: U33.7(2A) ; also on sheet 27
FSIRX2_DATA0: U33.10(3B2) ; also on sheet 27
FSIRX2_DATA0/MCAN5_RXD: U33.9(3A) ; also on sheet 27
FSIRX2_DATA1: U33.13(4B2) ; also on sheet 27
FSIRX2_DATA1/MCAN5_TXD: U33.12(4A) ; also on sheet 27
FSITX2_DATA1: U33.3(1B2) ; also on sheet 27
FSITX2_DATA1/MCAN4_RXD: U33.4(1A) ; also on sheet 27
GPIO_ICSSM1_RST: U1.N18(GPIO35) ; also on sheet 15
GPIO_ICSSM2_RST: U1.M18(GPIO36) ; also on sheet 7
GPIO_uSD_PWR_EN: U60.8(P07) ; also on sheet 25
HSEC_GPIO: U60.17(P20) ; also on sheet 6
HSEC_MCAN5_RX: U33.11(3B1) ; also on sheet 6
HSEC_MCAN5_TX: U33.14(4B1) ; also on sheet 6
I2C0_MUX_SEL: U60.10(P11) ; also on sheet 26
ICSSM0_MUX_SEL: U60.21(P24) ; also on sheet 32
ICSSM1_MUX_SEL: U60.3(P02) ; also on sheet 32
ICSSM2_MUX_SEL: U60.4(P03) ; also on sheet 33
IO_EXP_INTn: R395.1 U60.32(~{INT})
LIN_MUX_SEL: U60.14(P15) ; also on sheet 9
MCAN1_STB: R466.2 U29.14(nSTB) U60.18(P21)
MCAN4_CAN_H: J5.1 R171.1 U29.13(CANH)
MCAN4_CAN_L: J5.3 R174.2 U29.12(CANL)
MCAN4_RX: R173.1 U33.2(1B1)
MCAN4_RX_R: R173.2 U29.4(RxD)
MCAN4_T: C176.1 R171.2 R174.1
MCAN4_TX: R172.2 U33.5(2B1)
MCAN4_TX_R: R172.1 U29.1(TxD)
MCAN_EN: R1647.2 U29.6(EN)
MDIO0_MDC: R436.2 U1.M17(GPIO42) ; also on sheet 7 15
MDIO0_MDIO: R437.2 U1.N16(GPIO41) ; also on sheet 7 15
MDIO/MDC_MUX_SEL1: U60.19(P22) ; also on sheet 15
MDIO/MDC_MUX_SEL2: U60.20(P23) ; also on sheet 7
OSPI/QSPI_MUX_SEL: U1.P16(GPIO37) ; also on sheet 24
PMIC_INTn: U1.R17(GPIO29) ; also on sheet 30
PMIC_NRST: R432.1 ; also on sheet 30
PMIC_WKUP2: J22.1 ; also on sheet 6 30
PORZ: R327.1 TP75.1(TP) U79.4(Y) ; also on sheet 6 7 15 24 27
PORz_RST: R427.2 U76.7(1Y) U78.3(B)
PORz_VMAIN: U78.4(Y) U79.1(A)
RESETz: R428.2 U76.2(3Y) ; also on sheet 27
SOC_BOOTMODE0: U48.15(1B1) ; also on sheet 24
SOC_BOOTMODE1: U48.14(1B2) ; also on sheet 24
SOC_BOOTMODE2: U48.13(2B1) ; also on sheet 26
SOC_BOOTMODE3: U48.12(2B2) ; also on sheet 26
SOC_I2C2_SCL: U59.15(SCL) U60.29(SCL) ; also on sheet 1 26 28
SOC_I2C2_SDA: U59.2(SDA) U60.30(SDA) ; also on sheet 1 26 28
SOC_INTn: R544.2 U76.5(2Y) ; also on sheet 26
SPI1_MUX_SEL: U60.11(P12) ; also on sheet 30
SW_PB_INTn: Q10.2(S) R542.2 SW11.2
SW_PB_PORz: Q9.2(S) R541.2 SW10.2
SW_PB_RESETz: Q11.2(S) R543.2 SW12.2
SYS_BOOTMODE0: R323.2 SW6.1 U47.2(P0) U48.6(1A1)
SYS_BOOTMODE1: R324.2 SW6.2 U47.3(P1) U48.7(1A2)
SYS_BOOTMODE2: R325.2 SW6.3 U47.4(P2) U48.8(2A1)
SYS_BOOTMODE3: R326.2 SW6.4 U47.5(P3) U48.9(2A2)
SYSBOOT_BUF_ENz: R328.1 U49.2(B)
TA_GPIO1: Q10.1(G) ; also on sheet 3 28
TA_GPIO3: J12.1 U49.1(A) ; also on sheet 3 28
TA_GPIO4: U47.1(~{RESET}) ; also on sheet 3 28
TA_PORZn: Q9.1(G) ; also on sheet 3 28
TA_RESETz: Q11.1(G) ; also on sheet 3 28
TCAN_WAKE: R31.2 U29.9(WAKE)
UART2_MUX_SEL: U60.12(P13) ; also on sheet 26
VMAIN: R433.1 ; also on sheet 1 4 14 26 27 29
VMAIN_12V0: C348.2 R175.1 U29.10(VSUP) ; also on sheet 4 30
VMAIN_MON: R433.2 R434.1 U79.2(B)
VPP_LDO_EN: U60.13(P14) ; also on sheet 29
VSYS_1V2_PG: U78.1(A) ; also on sheet 1 29
VSYS_3V3_LDO1: C175.2 C243.1 C277.1 C278.1 C335.1 C340.1 C341.1 R392.2 R395.2 R425.1 R426.1 R427.1 R428.1 R429.1 R431.1 R436.1 R437.1 R466.1 R544.1 R1647.1 U29.5(VIO) U48.2(VCCB) U60.27(VCCP) U60.31(VCC) U76.8(VCC) U78.5(VCC) U79.5(VCC) ; also on sheet 1 6 7 9 14 15 16 17 24 26 27 28 29 30 32 33
VSYS_3V3_LDO2: C188.1 C276.1 R204.1 U33.16(VCC) U59.1(VCC) ; also on sheet 1 9 25 26 30
VSYS_TA_3V3: C242.1 C244.1 C245.2 C246.2 R316.1 R317.1 R318.1 R319.1 R320.2 R321.2 R322.2 U47.14(VCCP) U47.15(VCCI) U48.3(VCCA) U49.5(VCC) U50.5(VCC) ; also on sheet 1 3 28 29
WARMRESETn: R394.1 ; also on sheet 25 27
N32133653: R329.2 U49.4(Y)
N32133735: R319.2 SW6.5
N32133737: R318.2 SW6.6
N32133754: R317.2 SW6.7
N32133756: R316.2 SW6.8
N32302430: C336.1 R425.2 SW10.4
N32359377: C338.1 R429.2 SW12.4
N32360252: C337.1 R426.2 SW11.4
N32800162: R321.1 U47.16(ADDR)
N32800169: R320.1 U47.11(~{INT})
N32801024: LD11.2(ANODE) R381.1
N32801040: LD12.2(ANODE) R382.1
N32801094: LD13.2(ANODE) R383.1
N32801104: LD14.2(ANODE) R384.1
N32801160: LD15.2(ANODE) R385.1
N32801170: LD16.2(ANODE) R386.1
N32801226: LD17.2(ANODE) R387.1
N32801236: LD18.2(ANODE) R388.1
N32801519: R389.2 U59.9(A0)
N32801526: R390.2 U59.10(A1)
N32801533: R391.2 U59.7(A2)
N32817219: R392.1 R393.2 U60.26(ADDR)
N32817226: R394.2 U60.28(~{RESET})
N32851242: J12.2 R331.1
N32911629: C377.2 R541.1 U76.1(1A)
N32911790: C378.2 R542.1 U76.3(2A)
N33235493: R328.2 U50.4(Y)
N33514520: C247.1 R327.2 U50.2(A)
N34853373: C379.2 R543.1 U76.6(3A)
N34869480: R431.2 R432.2 U78.6(C)
N35271296: TP78.1(TP) U29.8(nFAULT)
N35376496: J21.1 R31.1 R175.2
N35387120: R116.1 U29.7(INH)
N35712813: J22.2 R116.2

Not connected (* = marked no-connect by the designer): U29 11(NC)*; U47 7(P4) 8(P5) 9(P6) 10(P7); U50 1(NC)*; U60 1(P00)* 22(P25)* 23(P26)* 24(P27)*

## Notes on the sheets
sheet 10
- RESET SWITCHES
- From Test Automation header
- SILK: "PORZ"
- From Test Automation header
- SILK: "INTn"
- SILK: "RESETn"
- PORz
sheet 11
- BOOTMODE BUFFER AND SWITCH
- SWITCH ON  =  LOGIC 1
  SWITCH OFF =  LOGIC 0
- DIR = H: A -> B
- I2C ADDRESS: 0x21
- BOOTMODE Control
  from Test
  Automation HDR
- PORZ
- TA_GPIO3
- HIGH
- LOW
- Enabled
- HIGH
- HIGH
- Disabled
- SH-J1 Shall be mounted to
  enable the bootmode buffer
sheet 12
- LED Driver
- I2C ADDRESS: 0x60
- IO Expander
- Symbol needs to get updated
- I2C ADDRESS: 0x22
sheet 13
- MCAN Interface
- CAD NOTE: DON'T ROUTE MCAN4_H AND MCAN4_L AS DIFFERENTIAL PAIR
- NOTE: ADD JUMPERS ACROSS J21 & J22 LOCATIONS TO ENABLE PMIC VIA WAKE2 PIN OF PMIC
- 120E
- PCB Silkscreen:
   "MCAN4"
- MCAN AND FSI MUX
- FSI MUX
- SEL
- CONDITION
- FUNCTION
- LOW
- MCAN for CAN & HSEC SELECTED
- A-->B1 port
- HIGH
- FSI SELECTED
- A-->B2 port
